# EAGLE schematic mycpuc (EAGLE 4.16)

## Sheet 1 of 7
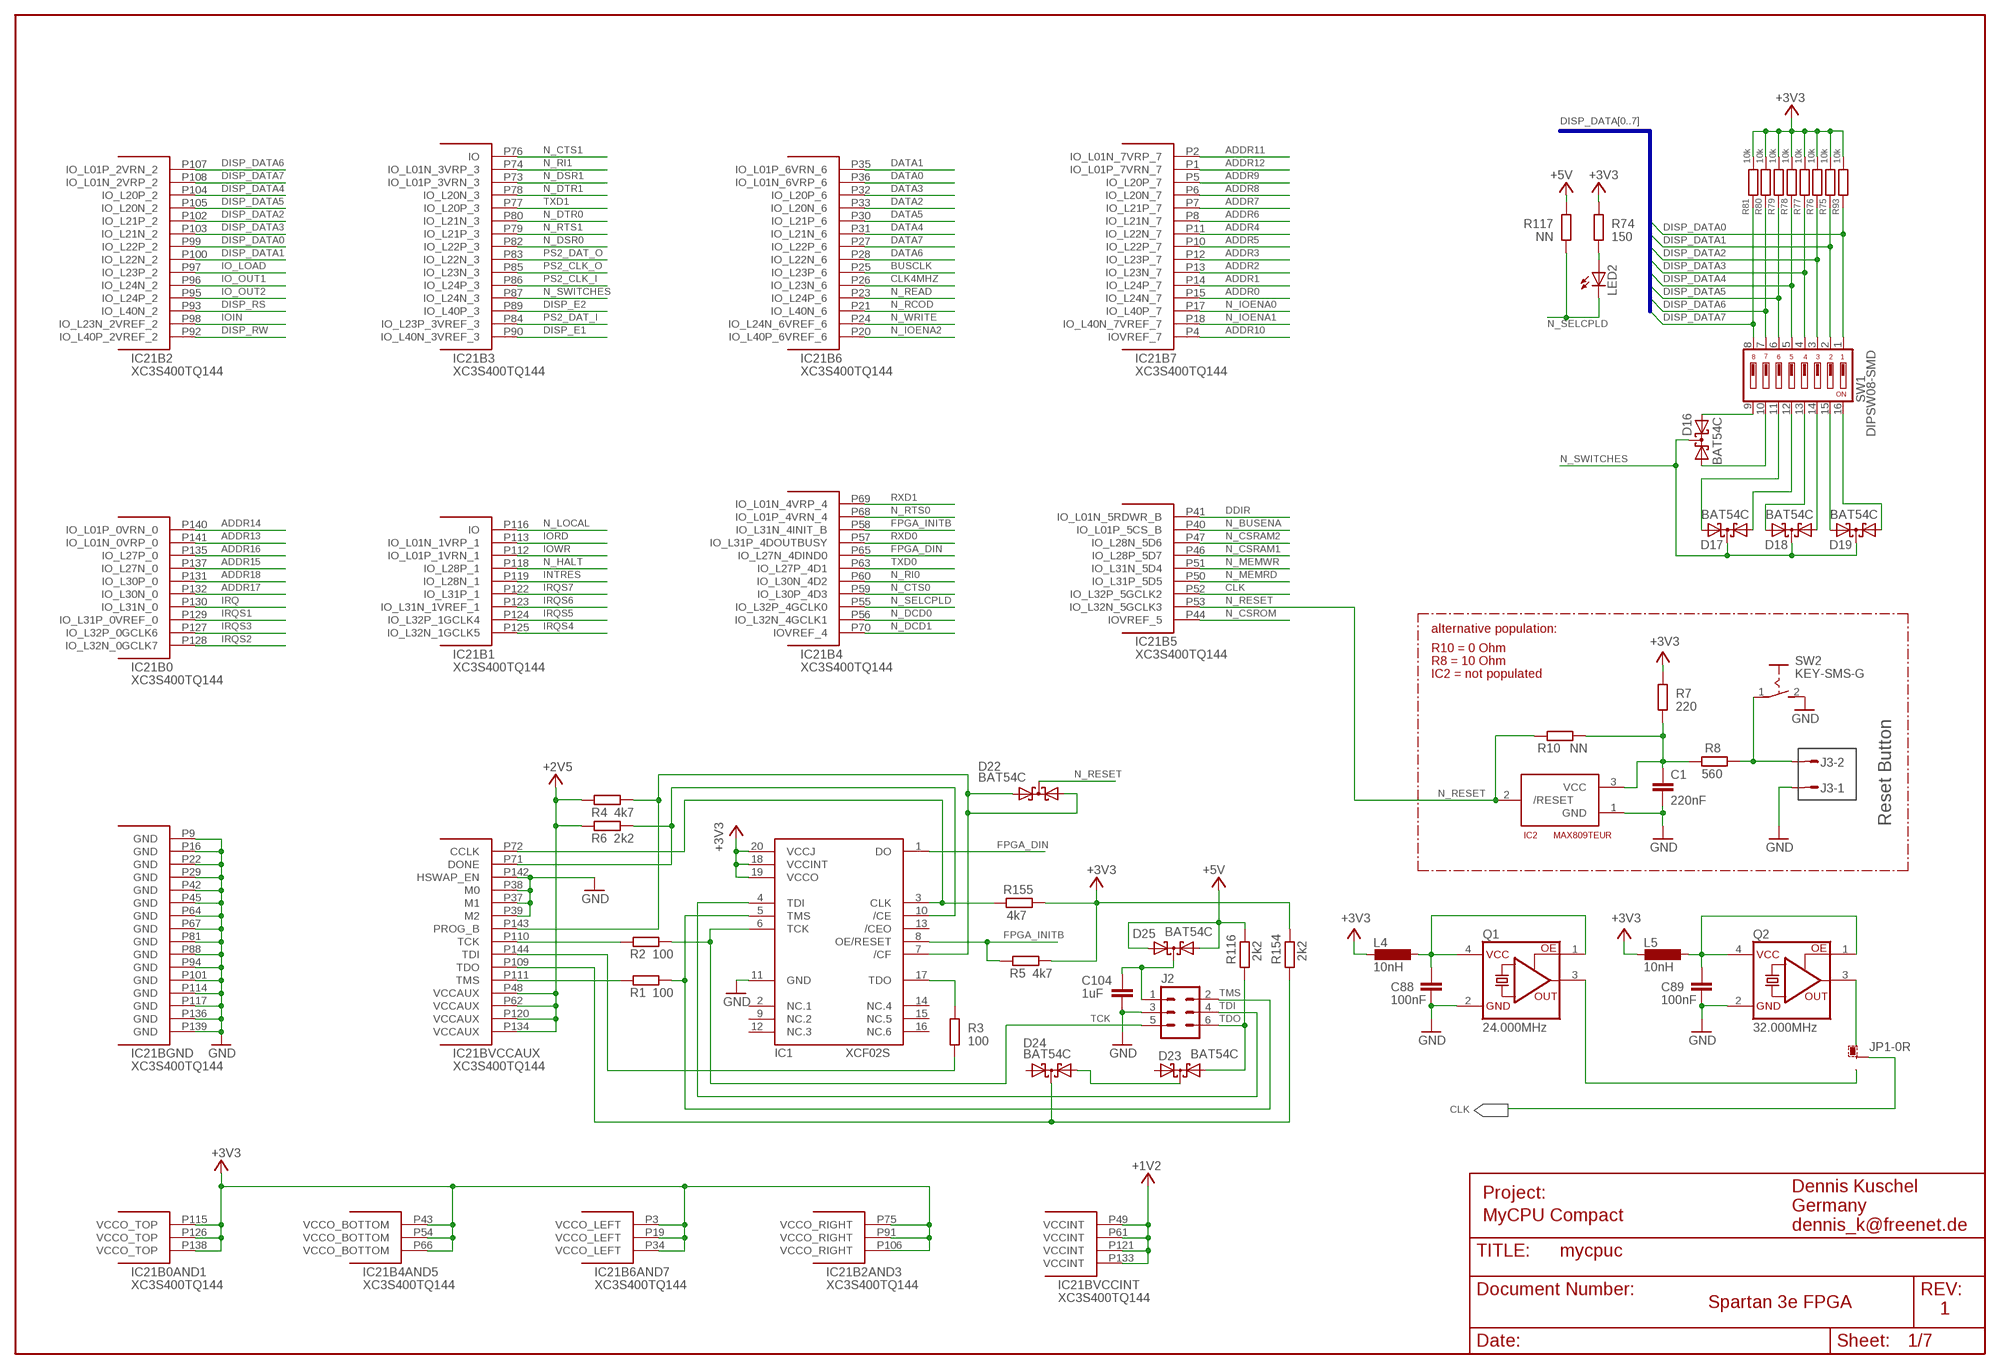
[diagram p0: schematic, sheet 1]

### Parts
C1  220nF  C-EUC0805  [C0805]
C88  100nF  C-EUC0805  [C0805]
C89  100nF  C-EUC0805  [C0805]
C104  1uF  C-EUC0805  [C0805]
D16  BAT54C  BAS40-05  [SOT23]
D17  BAT54C  BAS40-05  [SOT23]
D18  BAT54C  BAS40-05  [SOT23]
D19  BAT54C  BAS40-05  [SOT23]
D22  BAT54C  BAS40-05  [SOT23]
D23  BAT54C  BAS40-05  [SOT23]
D24  BAT54C  BAS40-05  [SOT23]
D25  BAT54C  BAS40-05  [SOT23]
IC1  XCF02S  [VO20]
IC2  MAX809TEUR  MAX809  [SOT23]
IC21  XC3S400TQ144  [TQ144]
J2  ML6  [ML6]
J3  S02P  [S02P]
JP1  0R-JUMPA  [A0R-JMP]
L4  10nH  L-0805  [0805]
L5  10nH  L-0805  [0805]
LED2  LEDCHIP-LED0805  [CHIP-LED0805]
Q1  24.000MHz  XO91  [XO91]
Q2  32.000MHz  XO91  [XO91]
R1  100  R-EU_M0805  [M0805]
R2  100  R-EU_M0805  [M0805]
R3  100  R-EU_M0805  [M0805]
R4  4k7  R-EU_M0805  [M0805]
R5  4k7  R-EU_M0805  [M0805]
R6  2k2  R-EU_M0805  [M0805]
R7  220  R-EU_M0805  [M0805]
R8  560  R-EU_M0805  [M0805]
R10  NN  R-EU_M0805  [M0805]
R74  150  R-EU_M0805  [M0805]
R75  10k  R-EU_M0805  [M0805]
R76  10k  R-EU_M0805  [M0805]
R77  10k  R-EU_M0805  [M0805]
R78  10k  R-EU_M0805  [M0805]
R79  10k  R-EU_M0805  [M0805]
R80  10k  R-EU_M0805  [M0805]
R81  10k  R-EU_M0805  [M0805]
R93  10k  R-EU_M0805  [M0805]
R116  2k2  R-EU_M0805  [M0805]
R117  NN  R-EU_M0805  [M0805]
R154  2k2  R-EU_M0805  [M0805]
R155  4k7  R-EU_M0805  [M0805]
SW1  DIPSW08-SMD  [DIPSW08]
SW2  KEY-SMS-G  [DIGIKEY-1]

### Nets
+1V2: IC21.P49(BVCCINT:VCCINT) IC21.P61(BVCCINT:VCCINT) IC21.P121(BVCCINT:VCCINT) IC21.P133(BVCCINT:VCCINT) ; also sheet 2
+2V5: IC21.P48(BVCCAUX:VCCAUX) IC21.P62(BVCCAUX:VCCAUX) IC21.P120(BVCCAUX:VCCAUX) IC21.P134(BVCCAUX:VCCAUX) R4.1 R6.1 ; also sheet 2
+3V3: IC1.18(VCCINT) IC1.19(VCCO) IC1.20(VCCJ) IC21.P3(B6AND7:VCCO_LEFT) IC21.P19(B6AND7:VCCO_LEFT) IC21.P34(B6AND7:VCCO_LEFT) IC21.P43(B4AND5:VCCO_BOTTOM) IC21.P54(B4AND5:VCCO_BOTTOM) IC21.P66(B4AND5:VCCO_BOTTOM) IC21.P75(B2AND3:VCCO_RIGHT) IC21.P91(B2AND3:VCCO_RIGHT) IC21.P106(B2AND3:VCCO_RIGHT) IC21.P115(B0AND1:VCCO_TOP) IC21.P126(B0AND1:VCCO_TOP) IC21.P138(B0AND1:VCCO_TOP) L4.2 L5.2 R5.2 R7.2 R74.2 R75.2 R76.2 R77.2 R78.2 R79.2 R80.2 R81.2 R93.2 R154.2 R155.2 ; also sheet 2,3,4,5
+5V: D25.1(A1) D25.2(A2) R116.2 R117.2 ; also sheet 2,3,5,6,7
ADDR0: IC21.P15(B7:IO_L24N_7) ; also sheet 3,4
ADDR1: IC21.P14(B7:IO_L24P_7) ; also sheet 3,4
ADDR2: IC21.P13(B7:IO_L23N_7) ; also sheet 3,4
ADDR3: IC21.P12(B7:IO_L23P_7) ; also sheet 3,4
ADDR4: IC21.P11(B7:IO_L22N_7) ; also sheet 3,4
ADDR5: IC21.P10(B7:IO_L22P_7) ; also sheet 3,4
ADDR6: IC21.P8(B7:IO_L21N_7) ; also sheet 3,4
ADDR7: IC21.P7(B7:IO_L21P_7) ; also sheet 3,4
ADDR8: IC21.P6(B7:IO_L20N_7) ; also sheet 3,4
ADDR9: IC21.P5(B7:IO_L20P_7) ; also sheet 3,4
ADDR10: IC21.P4(B7:IOVREF_7) ; also sheet 3,4
ADDR11: IC21.P2(B7:IO_L01N_7VRP_7) ; also sheet 3,4
ADDR12: IC21.P1(B7:IO_L01P_7VRN_7) ; also sheet 3,4
ADDR13: IC21.P141(B0:IO_L01N_0VRP_0) ; also sheet 3,4
ADDR14: IC21.P140(B0:IO_L01P_0VRN_0) ; also sheet 3,4
ADDR15: IC21.P137(B0:IO_L27N_0) ; also sheet 3,4
ADDR16: IC21.P135(B0:IO_L27P_0) ; also sheet 4
ADDR17: IC21.P132(B0:IO_L30N_0) ; also sheet 4
ADDR18: IC21.P131(B0:IO_L30P_0) ; also sheet 4
BUSCLK: IC21.P25(B6:IO_L23P_6) ; also sheet 3
CLK: IC21.P52(B5:IO_L32P_5GCLK2) JP1.2
CLK4MHZ: IC21.P26(B6:IO_L23N_6) ; also sheet 3,5
DATA0: IC21.P36(B6:IO_L01N_6VRP_6) ; also sheet 3,4
DATA1: IC21.P35(B6:IO_L01P_6VRN_6) ; also sheet 3,4
DATA2: IC21.P33(B6:IO_L20N_6) ; also sheet 3,4
DATA3: IC21.P32(B6:IO_L20P_6) ; also sheet 3,4
DATA4: IC21.P31(B6:IO_L21N_6) ; also sheet 3,4
DATA5: IC21.P30(B6:IO_L21P_6) ; also sheet 3,4
DATA6: IC21.P28(B6:IO_L22N_6) ; also sheet 3,4
DATA7: IC21.P27(B6:IO_L22P_6) ; also sheet 3,4
DDIR: IC21.P41(B5:IO_L01N_5RDWR_B) ; also sheet 3
DISP_DATA0: IC21.P99(B2:IO_L22P_2) R93.1 SW1.1 ; also sheet 5
DISP_DATA1: IC21.P100(B2:IO_L22N_2) R75.1 SW1.2 ; also sheet 5
DISP_DATA2: IC21.P102(B2:IO_L21P_2) R76.1 SW1.3 ; also sheet 5
DISP_DATA3: IC21.P103(B2:IO_L21N_2) R77.1 SW1.4 ; also sheet 5
DISP_DATA4: IC21.P104(B2:IO_L20P_2) R78.1 SW1.5 ; also sheet 5
DISP_DATA5: IC21.P105(B2:IO_L20N_2) R79.1 SW1.6 ; also sheet 5
DISP_DATA6: IC21.P107(B2:IO_L01P_2VRN_2) R80.1 SW1.7 ; also sheet 5
DISP_DATA7: IC21.P108(B2:IO_L01N_2VRP_2) R81.1 SW1.8 ; also sheet 5
DISP_E1: IC21.P90(B3:IO_L40N_3VREF_3) ; also sheet 5
DISP_E2: IC21.P89(B3:IO_L40P_3) ; also sheet 5
DISP_RS: IC21.P93(B2:IO_L40N_2) ; also sheet 5
DISP_RW: IC21.P92(B2:IO_L40P_2VREF_2) ; also sheet 5
FPGA_DIN: IC1.1(DO) IC21.P65(B4:IO_L27N_4DIND0)
FPGA_INITB: IC1.8(OE/RESET) IC21.P58(B4:IO_L31N_4INIT_B) R5.1 ; also sheet 7
GND: C1.2 C88.2 C89.2 C104.2 IC1.11(GND) IC2.1(GND) IC21.P9(BGND:GND) IC21.P16(BGND:GND) IC21.P22(BGND:GND) IC21.P29(BGND:GND) IC21.P37(BVCCAUX:M1) IC21.P38(BVCCAUX:M0) IC21.P39(BVCCAUX:M2) IC21.P42(BGND:GND) IC21.P45(BGND:GND) IC21.P64(BGND:GND) IC21.P67(BGND:GND) IC21.P81(BGND:GND) IC21.P88(BGND:GND) IC21.P94(BGND:GND) IC21.P101(BGND:GND) IC21.P114(BGND:GND) IC21.P117(BGND:GND) IC21.P136(BGND:GND) IC21.P139(BGND:GND) IC21.P142(BVCCAUX:HSWAP_EN) J2.3 J3.1 Q1.2(GND) Q2.2(GND) SW2.2 ; also sheet 2,3,4,5,6,7
INTRES: IC21.P119(B1:IO_L28N_1) ; also sheet 3
IO_LOAD: IC21.P97(B2:IO_L23P_2) ; also sheet 5
IO_OUT1: IC21.P96(B2:IO_L24N_2) ; also sheet 5
IO_OUT2: IC21.P95(B2:IO_L24P_2) ; also sheet 5
IOIN: IC21.P98(B2:IO_L23N_2VREF_2) ; also sheet 3,6
IORD: IC21.P113(B1:IO_L01N_1VRP_1) ; also sheet 3
IOWR: IC21.P112(B1:IO_L01P_1VRN_1) ; also sheet 3
IRQ: IC21.P130(B0:IO_L31N_0) ; also sheet 3
IRQS1: IC21.P129(B0:IO_L31P_0VREF_0) ; also sheet 3
IRQS2: IC21.P128(B0:IO_L32N_0GCLK7) ; also sheet 3
IRQS3: IC21.P127(B0:IO_L32P_0GCLK6) ; also sheet 3
IRQS4: IC21.P125(B1:IO_L32N_1GCLK5) ; also sheet 3
IRQS5: IC21.P124(B1:IO_L32P_1GCLK4) ; also sheet 3
IRQS6: IC21.P123(B1:IO_L31N_1VREF_1) ; also sheet 3
IRQS7: IC21.P122(B1:IO_L31P_1) ; also sheet 3
N$1: J3.2 R8.2 SW2.1
N$2: IC1.3(CLK) IC21.P72(BVCCAUX:CCLK) R155.1
N$3: IC1.10(/CE) IC21.P71(BVCCAUX:DONE) R6.2
N$4: IC21.P111(BVCCAUX:TMS) R1.1
N$5: IC21.P110(BVCCAUX:TCK) R2.1
N$6: C1.1 IC2.3(VCC) R7.1 R8.1 R10.2
N$8: IC1.17(TDO) R3.2
N$9: IC21.P144(BVCCAUX:TDI) R3.1
N$10: D22.1(A1) D22.2(A2) IC1.7(/CF) IC21.P143(BVCCAUX:PROG_B) R4.2
N$19: C104.1 D25.3(C) J2.1
N$52: LED2.A R74.1
N$53: D16.2(A2) SW1.9
N$54: D16.1(A1) SW1.10
N$55: D17.2(A2) SW1.11
N$56: D17.1(A1) SW1.12
N$57: D18.2(A2) SW1.13
N$58: D18.1(A1) SW1.14
N$59: D19.2(A2) SW1.15
N$60: D19.1(A1) SW1.16
N$65: JP1.1 Q2.3(FO)
N$66: JP1.3 Q1.3(FO)
N$103: D23.3(C) D24.1(A1)
N_BUSENA: IC21.P40(B5:IO_L01P_5CS_B) ; also sheet 3
N_CSRAM1: IC21.P46(B5:IO_L28P_5D7) ; also sheet 4
N_CSRAM2: IC21.P47(B5:IO_L28N_5D6) ; also sheet 4
N_CSROM: IC21.P44(B5:IOVREF_5) ; also sheet 4
N_CTS0: IC21.P59(B4:IO_L30P_4D3) ; also sheet 5
N_CTS1: IC21.P76(B3:IO) ; also sheet 5
N_DCD0: IC21.P56(B4:IO_L32N_4GCLK1) ; also sheet 5
N_DCD1: IC21.P70(B4:IOVREF_4) ; also sheet 5
N_DSR0: IC21.P82(B3:IO_L22P_3) ; also sheet 5
N_DSR1: IC21.P73(B3:IO_L01P_3VRN_3) ; also sheet 5
N_DTR0: IC21.P80(B3:IO_L21N_3) ; also sheet 5
N_DTR1: IC21.P78(B3:IO_L20N_3) ; also sheet 5
N_HALT: IC21.P118(B1:IO_L28P_1) ; also sheet 3
N_IOENA0: IC21.P17(B7:IO_L40P_7) ; also sheet 3
N_IOENA1: IC21.P18(B7:IO_L40N_7VREF_7) ; also sheet 3
N_IOENA2: IC21.P20(B6:IO_L40P_6VREF_6) ; also sheet 3
N_LOCAL: IC21.P116(B1:IO) ; also sheet 3
N_MEMRD: IC21.P50(B5:IO_L31P_5D5) ; also sheet 4
N_MEMWR: IC21.P51(B5:IO_L31N_5D4) ; also sheet 4
N_RCOD: IC21.P21(B6:IO_L40N_6) ; also sheet 3
N_READ: IC21.P23(B6:IO_L24P_6) ; also sheet 3
N_RESET: D22.3(C) IC2.2(/RESET) IC21.P53(B5:IO_L32N_5GCLK3) R10.1 ; also sheet 4
N_RI0: IC21.P60(B4:IO_L30N_4D2) ; also sheet 5
N_RI1: IC21.P74(B3:IO_L01N_3VRP_3) ; also sheet 5
N_RTS0: IC21.P68(B4:IO_L01P_4VRN_4) ; also sheet 5
N_RTS1: IC21.P79(B3:IO_L21P_3) ; also sheet 5
N_SELCPLD: IC21.P55(B4:IO_L32P_4GCLK0) LED2.C R117.1 ; also sheet 7
N_SWITCHES: D16.3(C) D17.3(C) D18.3(C) D19.3(C) IC21.P87(B3:IO_L24N_3)
N_WRITE: IC21.P24(B6:IO_L24N_6VREF_6) ; also sheet 3
PS2_CLK_I: IC21.P86(B3:IO_L24P_3) ; also sheet 5
PS2_CLK_O: IC21.P85(B3:IO_L23N_3) ; also sheet 5
PS2_DAT_I: IC21.P84(B3:IO_L23P_3VREF_3) ; also sheet 5
PS2_DAT_O: IC21.P83(B3:IO_L22N_3) ; also sheet 5
Q1_3V3: C88.1 L4.1 Q1.1(OE) Q1.4(VCC)
Q2_3V3: C89.1 L5.1 Q2.1(OE) Q2.4(VCC)
RXD0: IC21.P57(B4:IO_L31P_4DOUTBUSY) ; also sheet 5
RXD1: IC21.P69(B4:IO_L01N_4VRP_4) ; also sheet 5
TCK: IC1.6(TCK) J2.5 R2.2
TDI: IC1.4(TDI) J2.4
TDO: D24.3(C) IC21.P109(BVCCAUX:TDO) R154.1
TDO_JTAG: D23.1(A1) J2.6 R116.1
TMS: IC1.5(TMS) J2.2 R1.2
TXD0: IC21.P63(B4:IO_L27P_4D1) ; also sheet 5
TXD1: IC21.P77(B3:IO_L20P_3) ; also sheet 5
Unconnected: D23.2(A2) D24.2(A2) IC1.2(NC.1) IC1.9(NC.2) IC1.12(NC.3) IC1.13(/CEO) IC1.14(NC.4) IC1.15(NC.5) IC1.16(NC.6)

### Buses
DISP_DATA[0..7]

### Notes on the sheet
- alternative population:
- R10 = 0 Ohm
- R8 = 10 Ohm
- IC2 = not populated
- Reset Button
- Dennis Kuschel
- Project:
- Germany
- MyCPU Compact
- dennis_k@freenet.de
- Spartan 3e FPGA
- 1

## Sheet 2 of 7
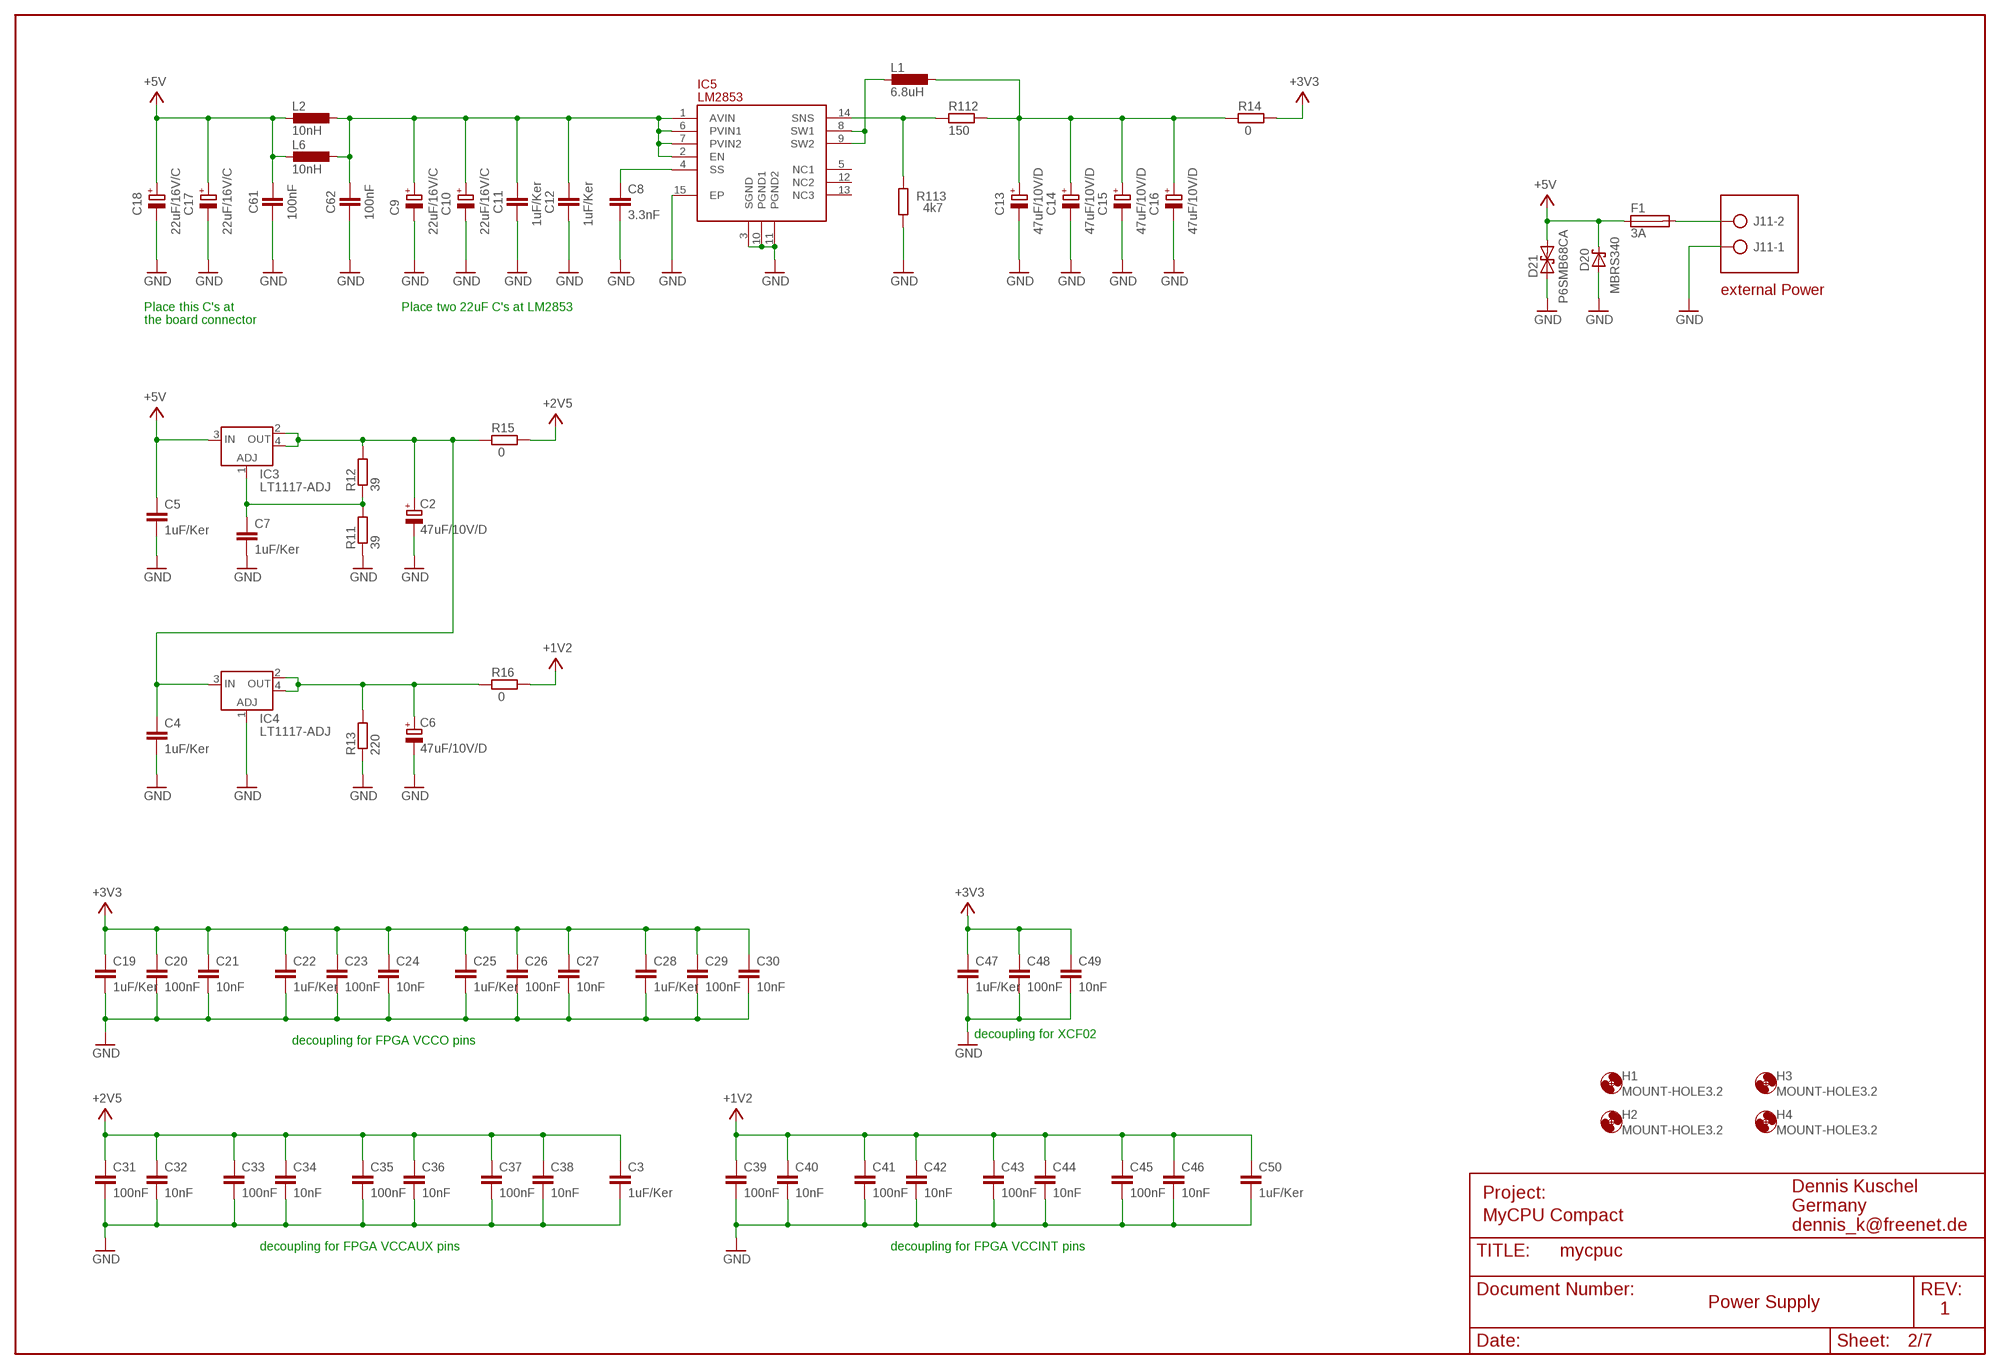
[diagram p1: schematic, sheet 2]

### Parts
C2  47uF/10V/D  CPOL-EUD/7343-31R  [D/7343-31R]
C3  1uF/Ker  C-EUC0805  [C0805]
C4  1uF/Ker  C-EUC0805  [C0805]
C5  1uF/Ker  C-EUC0805  [C0805]
C6  47uF/10V/D  CPOL-EUD/7343-31R  [D/7343-31R]
C7  1uF/Ker  C-EUC0805  [C0805]
C8  3.3nF  C-EUC0805  [C0805]
C9  22uF/16V/C  CPOL-EUC/6032-28R  [C/6032-28R]
C10  22uF/16V/C  CPOL-EUC/6032-28R  [C/6032-28R]
C11  1uF/Ker  C-EUC0805  [C0805]
C12  1uF/Ker  C-EUC0805  [C0805]
C13  47uF/10V/D  CPOL-EUD/7343-31R  [D/7343-31R]
C14  47uF/10V/D  CPOL-EUD/7343-31R  [D/7343-31R]
C15  47uF/10V/D  CPOL-EUD/7343-31R  [D/7343-31R]
C16  47uF/10V/D  CPOL-EUD/7343-31R  [D/7343-31R]
C17  22uF/16V/C  CPOL-EUC/6032-28R  [C/6032-28R]
C18  22uF/16V/C  CPOL-EUC/6032-28R  [C/6032-28R]
C19  1uF/Ker  C-EUC0805  [C0805]
C20  100nF  C-EUC0805  [C0805]
C21  10nF  C-EUC0805  [C0805]
C22  1uF/Ker  C-EUC0805  [C0805]
C23  100nF  C-EUC0805  [C0805]
C24  10nF  C-EUC0805  [C0805]
C25  1uF/Ker  C-EUC0805  [C0805]
C26  100nF  C-EUC0805  [C0805]
C27  10nF  C-EUC0805  [C0805]
C28  1uF/Ker  C-EUC0805  [C0805]
C29  100nF  C-EUC0805  [C0805]
C30  10nF  C-EUC0805  [C0805]
C31  100nF  C-EUC0805  [C0805]
C32  10nF  C-EUC0805  [C0805]
C33  100nF  C-EUC0805  [C0805]
C34  10nF  C-EUC0805  [C0805]
C35  100nF  C-EUC0805  [C0805]
C36  10nF  C-EUC0805  [C0805]
C37  100nF  C-EUC0805  [C0805]
C38  10nF  C-EUC0805  [C0805]
C39  100nF  C-EUC0805  [C0805]
C40  10nF  C-EUC0805  [C0805]
C41  100nF  C-EUC0805  [C0805]
C42  10nF  C-EUC0805  [C0805]
C43  100nF  C-EUC0805  [C0805]
C44  10nF  C-EUC0805  [C0805]
C45  100nF  C-EUC0805  [C0805]
C46  10nF  C-EUC0805  [C0805]
C47  1uF/Ker  C-EUC0805  [C0805]
C48  100nF  C-EUC0805  [C0805]
C49  10nF  C-EUC0805  [C0805]
C50  1uF/Ker  C-EUC0805  [C0805]
C61  100nF  C-EUC0805  [C0805]
C62  100nF  C-EUC0805  [C0805]
D20  MBRS340  [DO214AB]
D21  P6SMB68CA  [DO214AA]
F1  3A  FUSE-HASF  [HASF]
H1  MOUNT-HOLE3.2  [3,2]
H2  MOUNT-HOLE3.2  [3,2]
H3  MOUNT-HOLE3.2  [3,2]
H4  MOUNT-HOLE3.2  [3,2]
IC3  LT1117-ADJ  [SOT223]
IC4  LT1117-ADJ  [SOT223]
IC5  LM2853  [ETSSOP14]
J11  AK500/2  [AK500/2]
L1  6.8uH  DO3316P  [DO3316P]
L2  10nH  L-0805  [0805]
L6  10nH  L-0805  [0805]
R11  39  R-EU_R0805  [R0805]
R12  39  R-EU_R0805  [R0805]
R13  220  R-EU_R0805  [R0805]
R14  0  R-EU_R0805  [R0805]
R15  0  R-EU_R0805  [R0805]
R16  0  R-EU_R0805  [R0805]
R112  150  R-EU_R0805  [R0805]
R113  4k7  R-EU_R0805  [R0805]

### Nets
3V3OUT: C13.+ C14.+ C15.+ C16.+ L1.2 R14.1 R112.2
5V_SREG: C9.+ C10.+ C11.1 C12.1 C62.1 IC5.1(AVIN) IC5.2(EN) IC5.6(PVIN1) IC5.7(PVIN2) L2.1 L6.1
+1V2: C39.1 C40.1 C41.1 C42.1 C43.1 C44.1 C45.1 C46.1 C50.1 R16.2 ; also sheet 1
+2V5: C3.1 C31.1 C32.1 C33.1 C34.1 C35.1 C36.1 C37.1 C38.1 R15.2 ; also sheet 1
+3V3: C19.1 C20.1 C21.1 C22.1 C23.1 C24.1 C25.1 C26.1 C27.1 C28.1 C29.1 C30.1 C47.1 C48.1 C49.1 R14.2 ; also sheet 1,3,4,5
+5V: C5.1 C17.+ C18.+ C61.1 D20.K(C) D21.K(C) F1.1 IC3.3(IN) L2.2 L6.2 ; also sheet 1,3,5,6,7
GND: C2.- C3.2 C4.2 C5.2 C6.- C7.2 C8.2 C9.- C10.- C11.2 C12.2 C13.- C14.- C15.- C16.- C17.- C18.- C19.2 C20.2 C21.2 C22.2 C23.2 C24.2 C25.2 C26.2 C27.2 C28.2 C29.2 C30.2 C31.2 C32.2 C33.2 C34.2 C35.2 C36.2 C37.2 C38.2 C39.2 C40.2 C41.2 C42.2 C43.2 C44.2 C45.2 C46.2 C47.2 C48.2 C49.2 C50.2 C61.2 C62.2 D20.A D21.A IC4.1(ADJ) IC5.3(SGND) IC5.10(PGND1) IC5.11(PGND2) IC5.15(EP) J11.1 R11.1 R13.1 R113.1 ; also sheet 1,3,4,5,6,7
N$7: C7.1 IC3.1(ADJ) R11.2 R12.1
N$11: IC5.8(SW1) IC5.9(SW2) L1.1
N$13: C8.1 IC5.4(SS)
N$15: C6.+ IC4.2(OUT) IC4.4(OUT1) R13.2 R16.1
N$63: C2.+ C4.1 IC3.2(OUT) IC3.4(OUT1) IC4.3(IN) R12.2 R15.1
N$69: IC5.14(SNS) R112.1 R113.2
N$90: F1.2 J11.2
Unconnected: IC5.5(NC1) IC5.12(NC2) IC5.13(NC3)

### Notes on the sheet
- external Power
- Place this C's at | Place two 22uF C's at LM2853
- the board connector
- decoupling for XCF02
- decoupling for FPGA VCCO pins
- Dennis Kuschel
- Project:
- Germany
- MyCPU Compact
- dennis_k@freenet.de
- decoupling for FPGA VCCAUX pins | decoupling for FPGA VCCINT pins
- Power Supply
- 1

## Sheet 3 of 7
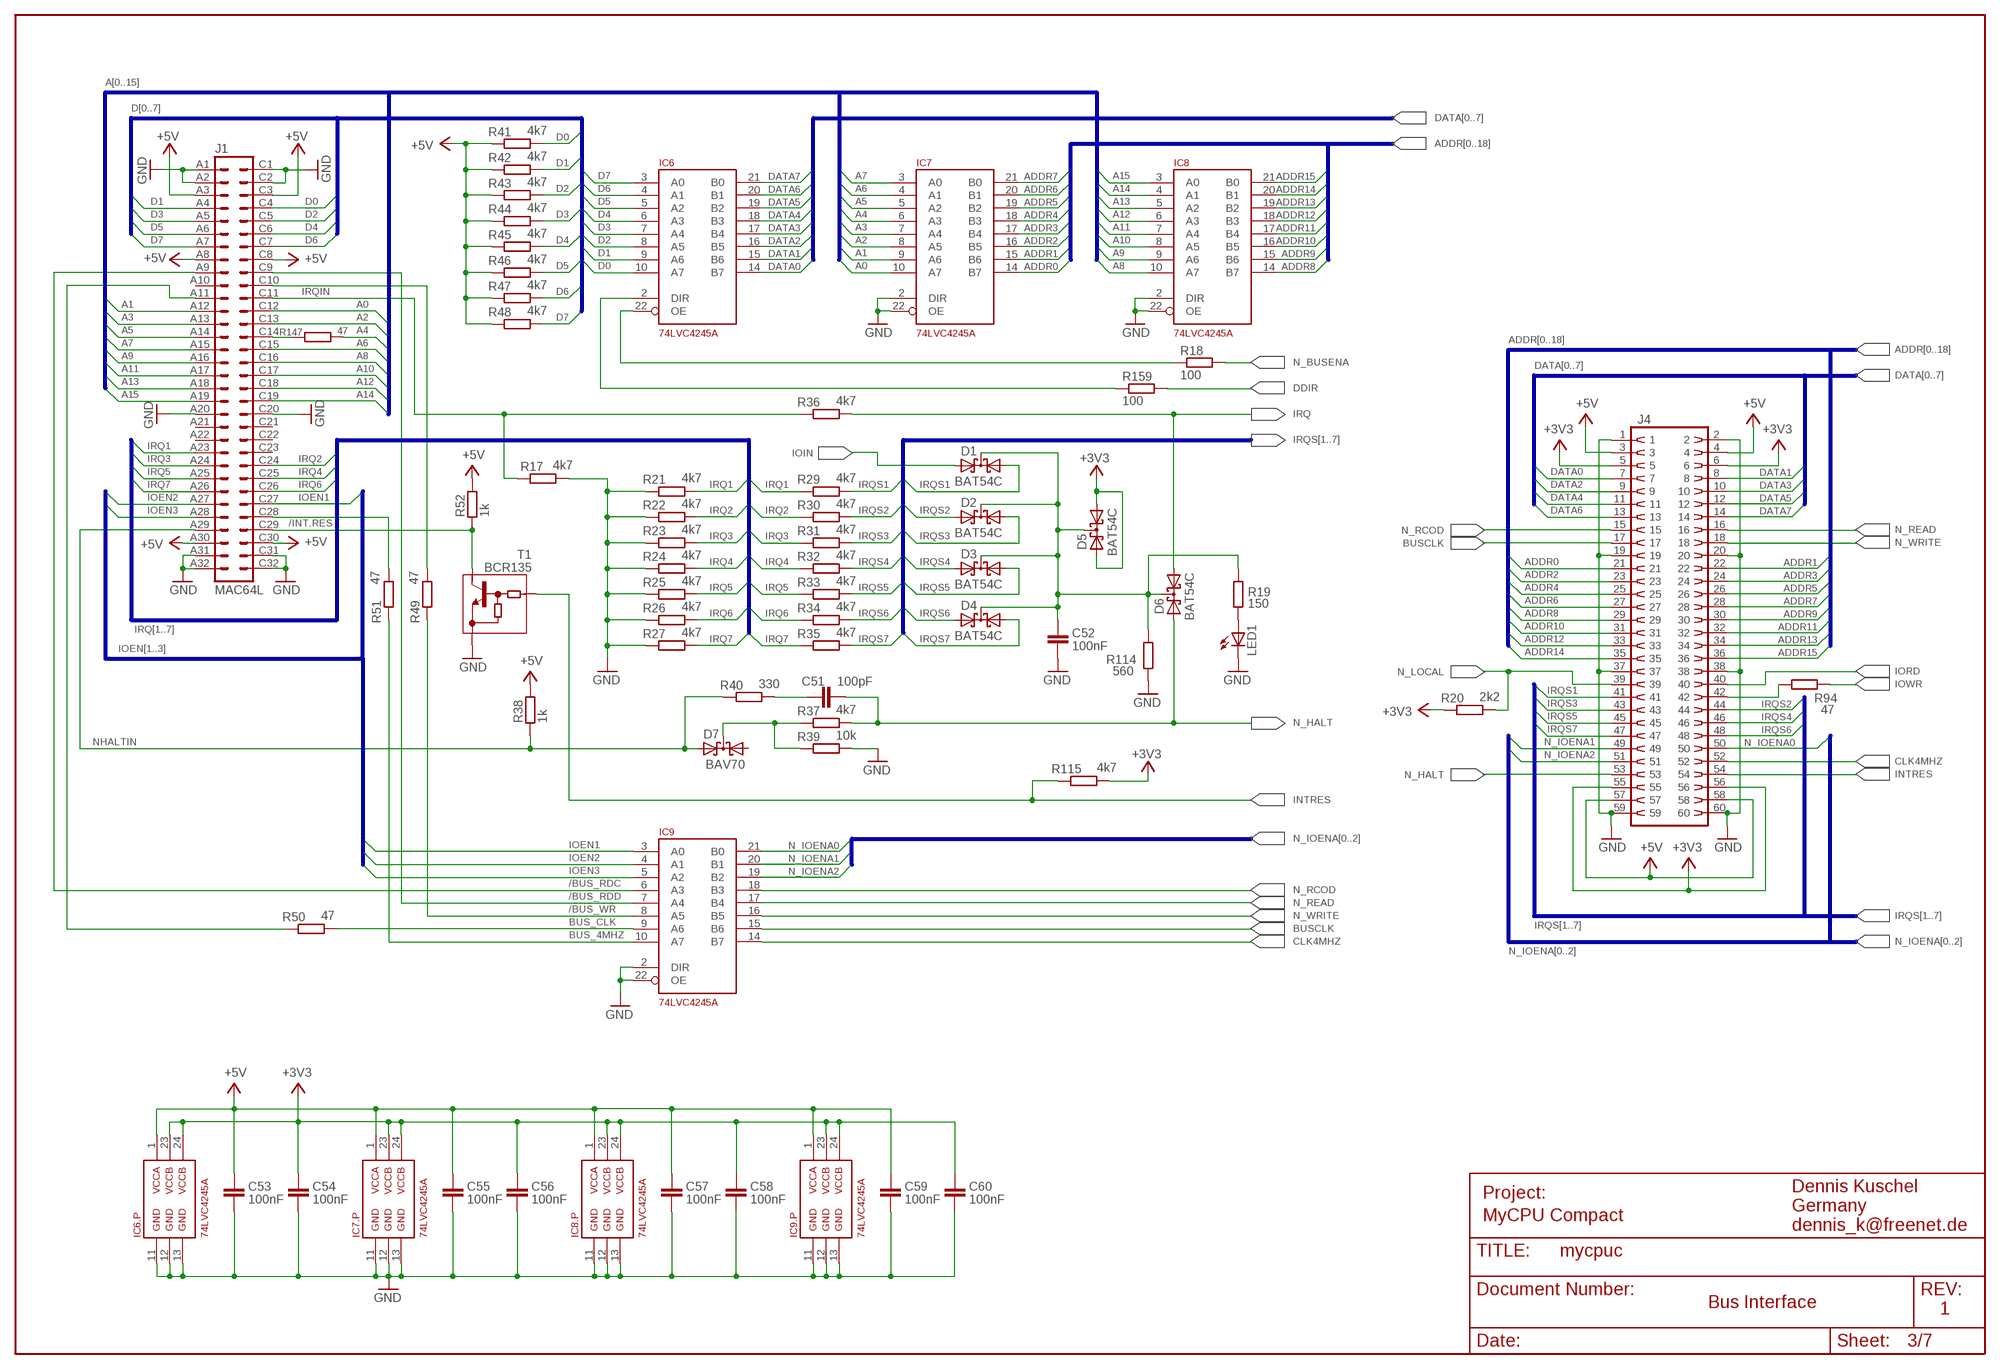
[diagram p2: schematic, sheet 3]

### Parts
C51  100pF  C-EUC0805  [C0805]
C52  100nF  C-EUC0805  [C0805]
C53  100nF  C-EUC0805  [C0805]
C54  100nF  C-EUC0805  [C0805]
C55  100nF  C-EUC0805  [C0805]
C56  100nF  C-EUC0805  [C0805]
C57  100nF  C-EUC0805  [C0805]
C58  100nF  C-EUC0805  [C0805]
C59  100nF  C-EUC0805  [C0805]
C60  100nF  C-EUC0805  [C0805]
D1  BAT54C  BAS40-05  [SOT23]
D2  BAT54C  BAS40-05  [SOT23]
D3  BAT54C  BAS40-05  [SOT23]
D4  BAT54C  BAS40-05  [SOT23]
D5  BAT54C  BAS40-05  [SOT23]
D6  BAT54C  BAS40-05  [SOT23]
D7  BAV70  BAS40-05  [SOT23]
IC6  74LVC4245A  [TSSOP24]
IC7  74LVC4245A  [TSSOP24]
IC8  74LVC4245A  [TSSOP24]
IC9  74LVC4245A  [TSSOP24]
J1  MAC64L  [MAC64L]
J4  BU60  [DIL2X30]
LED1  LEDCHIP-LED0805  [CHIP-LED0805]
R17  4k7  R-EU_R0805  [R0805]
R18  100  R-EU_R0805  [R0805]
R19  150  R-EU_R0805  [R0805]
R20  2k2  R-EU_R0805  [R0805]
R21  4k7  R-EU_R0805  [R0805]
R22  4k7  R-EU_R0805  [R0805]
R23  4k7  R-EU_R0805  [R0805]
R24  4k7  R-EU_R0805  [R0805]
R25  4k7  R-EU_R0805  [R0805]
R26  4k7  R-EU_R0805  [R0805]
R27  4k7  R-EU_R0805  [R0805]
R29  4k7  R-EU_R0805  [R0805]
R30  4k7  R-EU_R0805  [R0805]
R31  4k7  R-EU_R0805  [R0805]
R32  4k7  R-EU_R0805  [R0805]
R33  4k7  R-EU_R0805  [R0805]
R34  4k7  R-EU_R0805  [R0805]
R35  4k7  R-EU_R0805  [R0805]
R36  4k7  R-EU_R0805  [R0805]
R37  4k7  R-EU_R0805  [R0805]
R38  1k  R-EU_R0805  [R0805]
R39  10k  R-EU_R0805  [R0805]
R40  330  R-EU_R0805  [R0805]
R41  4k7  R-EU_R0805  [R0805]
R42  4k7  R-EU_R0805  [R0805]
R43  4k7  R-EU_R0805  [R0805]
R44  4k7  R-EU_R0805  [R0805]
R45  4k7  R-EU_R0805  [R0805]
R46  4k7  R-EU_R0805  [R0805]
R47  4k7  R-EU_R0805  [R0805]
R48  4k7  R-EU_R0805  [R0805]
R49  47  R-EU_R0805  [R0805]
R50  47  R-EU_R0805  [R0805]
R51  47  R-EU_R0805  [R0805]
R52  1k  R-EU_R0805  [R0805]
R94  47  R-EU_R0805  [R0805]
R114  560  R-EU_R0805  [R0805]
R115  4k7  R-EU_R0805  [R0805]
R147  47  R-EU_R0805  [R0805]
R159  100  R-EU_R0805  [R0805]
T1  BCR135  [SOT23]

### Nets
2V9: C52.1 D1.3(C) D2.3(C) D3.3(C) D4.3(C) D5.3(C) D6.3(C) R19.1 R114.1
4.000MHZ: J1.C28 R51.2
+3V3: C54.1 C56.1 C58.1 C60.1 D5.1(A1) D5.2(A2) IC6.23(VCCB.1) IC6.24(VCCB.2) IC7.23(VCCB.1) IC7.24(VCCB.2) IC8.23(VCCB.1) IC8.24(VCCB.2) IC9.23(VCCB.1) IC9.24(VCCB.2) J4.5 J4.6 J4.55 J4.56 R20.1 R115.2 ; also sheet 1,2,4,5
+5V: C53.1 C55.1 C57.1 C59.1 IC6.1(VCCA) IC7.1(VCCA) IC8.1(VCCA) IC9.1(VCCA) J1.A3 J1.A8 J1.A30 J1.C3 J1.C8 J1.C30 J4.3 J4.4 J4.57 J4.58 R38.2 R41.1 R42.1 R43.1 R44.1 R45.1 R46.1 R47.1 R48.1 R52.2 ; also sheet 1,2,5,6,7
/B_WR: J1.C10 R49.2
/BUS_RDC: IC9.6(A3) J1.A9
/BUS_RDD: IC9.7(A4) J1.C9 ; also sheet 7
/BUS_WR: IC9.8(A5) R49.1 ; also sheet 7
/INT.RES: J1.C29 R52.1 T1.3(C) ; also sheet 7
A0: IC7.10(A7) J1.C12 ; also sheet 7
A1: IC7.9(A6) J1.A12 ; also sheet 7
A2: IC7.8(A5) J1.C13 ; also sheet 7
A3: IC7.7(A4) J1.A13 ; also sheet 7
A4: IC7.6(A3) R147.2 ; also sheet 7
A4B: J1.C14 R147.1
A5: IC7.5(A2) J1.A14 ; also sheet 7
A6: IC7.4(A1) J1.C15
A7: IC7.3(A0) J1.A15
A8: IC8.10(A7) J1.C16 ; also sheet 7
A9: IC8.9(A6) J1.A16 ; also sheet 7
A10: IC8.8(A5) J1.C17
A11: IC8.7(A4) J1.A17
A12: IC8.6(A3) J1.C18
A13: IC8.5(A2) J1.A18
A14: IC8.4(A1) J1.C19
A15: IC8.3(A0) J1.A19
ADDR0: IC7.14(B7) J4.21 ; also sheet 1,4
ADDR1: IC7.15(B6) J4.22 ; also sheet 1,4
ADDR2: IC7.16(B5) J4.23 ; also sheet 1,4
ADDR3: IC7.17(B4) J4.24 ; also sheet 1,4
ADDR4: IC7.18(B3) J4.25 ; also sheet 1,4
ADDR5: IC7.19(B2) J4.26 ; also sheet 1,4
ADDR6: IC7.20(B1) J4.27 ; also sheet 1,4
ADDR7: IC7.21(B0) J4.28 ; also sheet 1,4
ADDR8: IC8.14(B7) J4.29 ; also sheet 1,4
ADDR9: IC8.15(B6) J4.30 ; also sheet 1,4
ADDR10: IC8.16(B5) J4.31 ; also sheet 1,4
ADDR11: IC8.17(B4) J4.32 ; also sheet 1,4
ADDR12: IC8.18(B3) J4.33 ; also sheet 1,4
ADDR13: IC8.19(B2) J4.34 ; also sheet 1,4
ADDR14: IC8.20(B1) J4.35 ; also sheet 1,4
ADDR15: IC8.21(B0) J4.36 ; also sheet 1,4
BUS_4MHZ: IC9.10(A7) R51.1
BUS_CLK: IC9.9(A6) R50.2
BUSCKOUT: J1.A11 R50.1
BUSCLK: IC9.15(B6) J4.17 ; also sheet 1
CLK4MHZ: IC9.14(B7) J4.52 ; also sheet 1,5
D0: IC6.10(A7) J1.C4 R41.2 ; also sheet 7
D1: IC6.9(A6) J1.A4 R42.2 ; also sheet 7
D2: IC6.8(A5) J1.C5 R43.2 ; also sheet 7
D3: IC6.7(A4) J1.A5 R44.2 ; also sheet 7
D4: IC6.6(A3) J1.C6 R45.2 ; also sheet 7
D5: IC6.5(A2) J1.A6 R46.2 ; also sheet 7
D6: IC6.4(A1) J1.C7 R47.2 ; also sheet 7
D7: IC6.3(A0) J1.A7 R48.2 ; also sheet 7
DATA0: IC6.14(B7) J4.7 ; also sheet 1,4
DATA1: IC6.15(B6) J4.8 ; also sheet 1,4
DATA2: IC6.16(B5) J4.9 ; also sheet 1,4
DATA3: IC6.17(B4) J4.10 ; also sheet 1,4
DATA4: IC6.18(B3) J4.11 ; also sheet 1,4
DATA5: IC6.19(B2) J4.12 ; also sheet 1,4
DATA6: IC6.20(B1) J4.13 ; also sheet 1,4
DATA7: IC6.21(B0) J4.14 ; also sheet 1,4
DDIR: R159.2 ; also sheet 1
GND: C52.2 C53.2 C54.2 C55.2 C56.2 C57.2 C58.2 C59.2 C60.2 IC6.11(GND.1) IC6.12(GND.2) IC6.13(GND.3) IC7.2(DIR) IC7.11(GND.1) IC7.12(GND.2) IC7.13(GND.3) IC7.22(OE) IC8.2(DIR) IC8.11(GND.1) IC8.12(GND.2) IC8.13(GND.3) IC8.22(OE) IC9.2(DIR) IC9.11(GND.1) IC9.12(GND.2) IC9.13(GND.3) IC9.22(OE) J1.A1 J1.A2 J1.A20 J1.A31 J1.A32 J1.C1 J1.C2 J1.C20 J1.C31 J1.C32 J4.1 J4.2 J4.19 J4.20 J4.37 J4.38 J4.59 J4.60 LED1.C R17.2 R21.1 R22.1 R23.1 R24.1 R25.1 R26.1 R27.1 R39.2 R114.2 T1.2(E) ; also sheet 1,2,4,5,6,7
INTRES: J4.54 R115.1 T1.1(B) ; also sheet 1
IOEN1: IC9.3(A0) J1.C27
IOEN2: IC9.4(A1) J1.A27
IOEN3: IC9.5(A2) J1.A28
IOIN: D1.2(A2) ; also sheet 1,6
IORD: J4.40 ; also sheet 1
IOWR: R94.2 ; also sheet 1
IOWR_R: J4.42 R94.1
IRQ: D6.1(A1) R36.2 ; also sheet 1
IRQ1: J1.A23 R21.2 R29.1
IRQ2: J1.C24 R22.2 R30.1
IRQ3: J1.A24 R23.2 R31.1
IRQ4: J1.C25 R24.2 R32.1
IRQ5: J1.A25 R25.2 R33.1
IRQ6: J1.C26 R26.2 R34.1
IRQ7: J1.A26 R27.2 R35.1
IRQIN: J1.C11 R17.1 R36.1
IRQS1: D1.1(A1) J4.41 R29.2 ; also sheet 1
IRQS2: D2.2(A2) J4.44 R30.2 ; also sheet 1
IRQS3: D2.1(A1) J4.43 R31.2 ; also sheet 1
IRQS4: D3.2(A2) J4.46 R32.2 ; also sheet 1
IRQS5: D3.1(A1) J4.45 R33.2 ; also sheet 1
IRQS6: D4.2(A2) J4.48 R34.2 ; also sheet 1
IRQS7: D4.1(A1) J4.47 R35.2 ; also sheet 1
N$16: IC6.22(OE) R18.1
N$17: C51.1 R40.2
N$18: D7.3(C) R37.1 R39.1
N$35: IC6.2(DIR) R159.1
N$51: LED1.A R19.2
N_BUSENA: R18.2 ; also sheet 1
N_HALT: C51.2 D6.2(A2) J4.53 R37.2 ; also sheet 1
N_IOENA0: IC9.21(B0) J4.50 ; also sheet 1
N_IOENA1: IC9.20(B1) J4.49 ; also sheet 1
N_IOENA2: IC9.19(B2) J4.51 ; also sheet 1
N_LOCAL: J4.39 R20.2 ; also sheet 1
N_RCOD: IC9.18(B3) J4.15 ; also sheet 1
N_READ: IC9.17(B4) J4.16 ; also sheet 1
N_WRITE: IC9.16(B5) J4.18 ; also sheet 1
NHALTIN: D7.2(A2) J1.A29 R38.1 R40.1
Unconnected: D7.1(A1) J1.A10 J1.A21 J1.A22 J1.C21 J1.C22 J1.C23

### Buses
D[0..7]
A[0..15]
IRQ[1..7]
IOEN[1..3]
ADDR[0..18]
DATA[0..7]
IRQS[1..7]
N_IOENA[0..2]

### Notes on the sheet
- Dennis Kuschel
- Project:
- Germany
- MyCPU Compact
- dennis_k@freenet.de
- Bus Interface
- 1

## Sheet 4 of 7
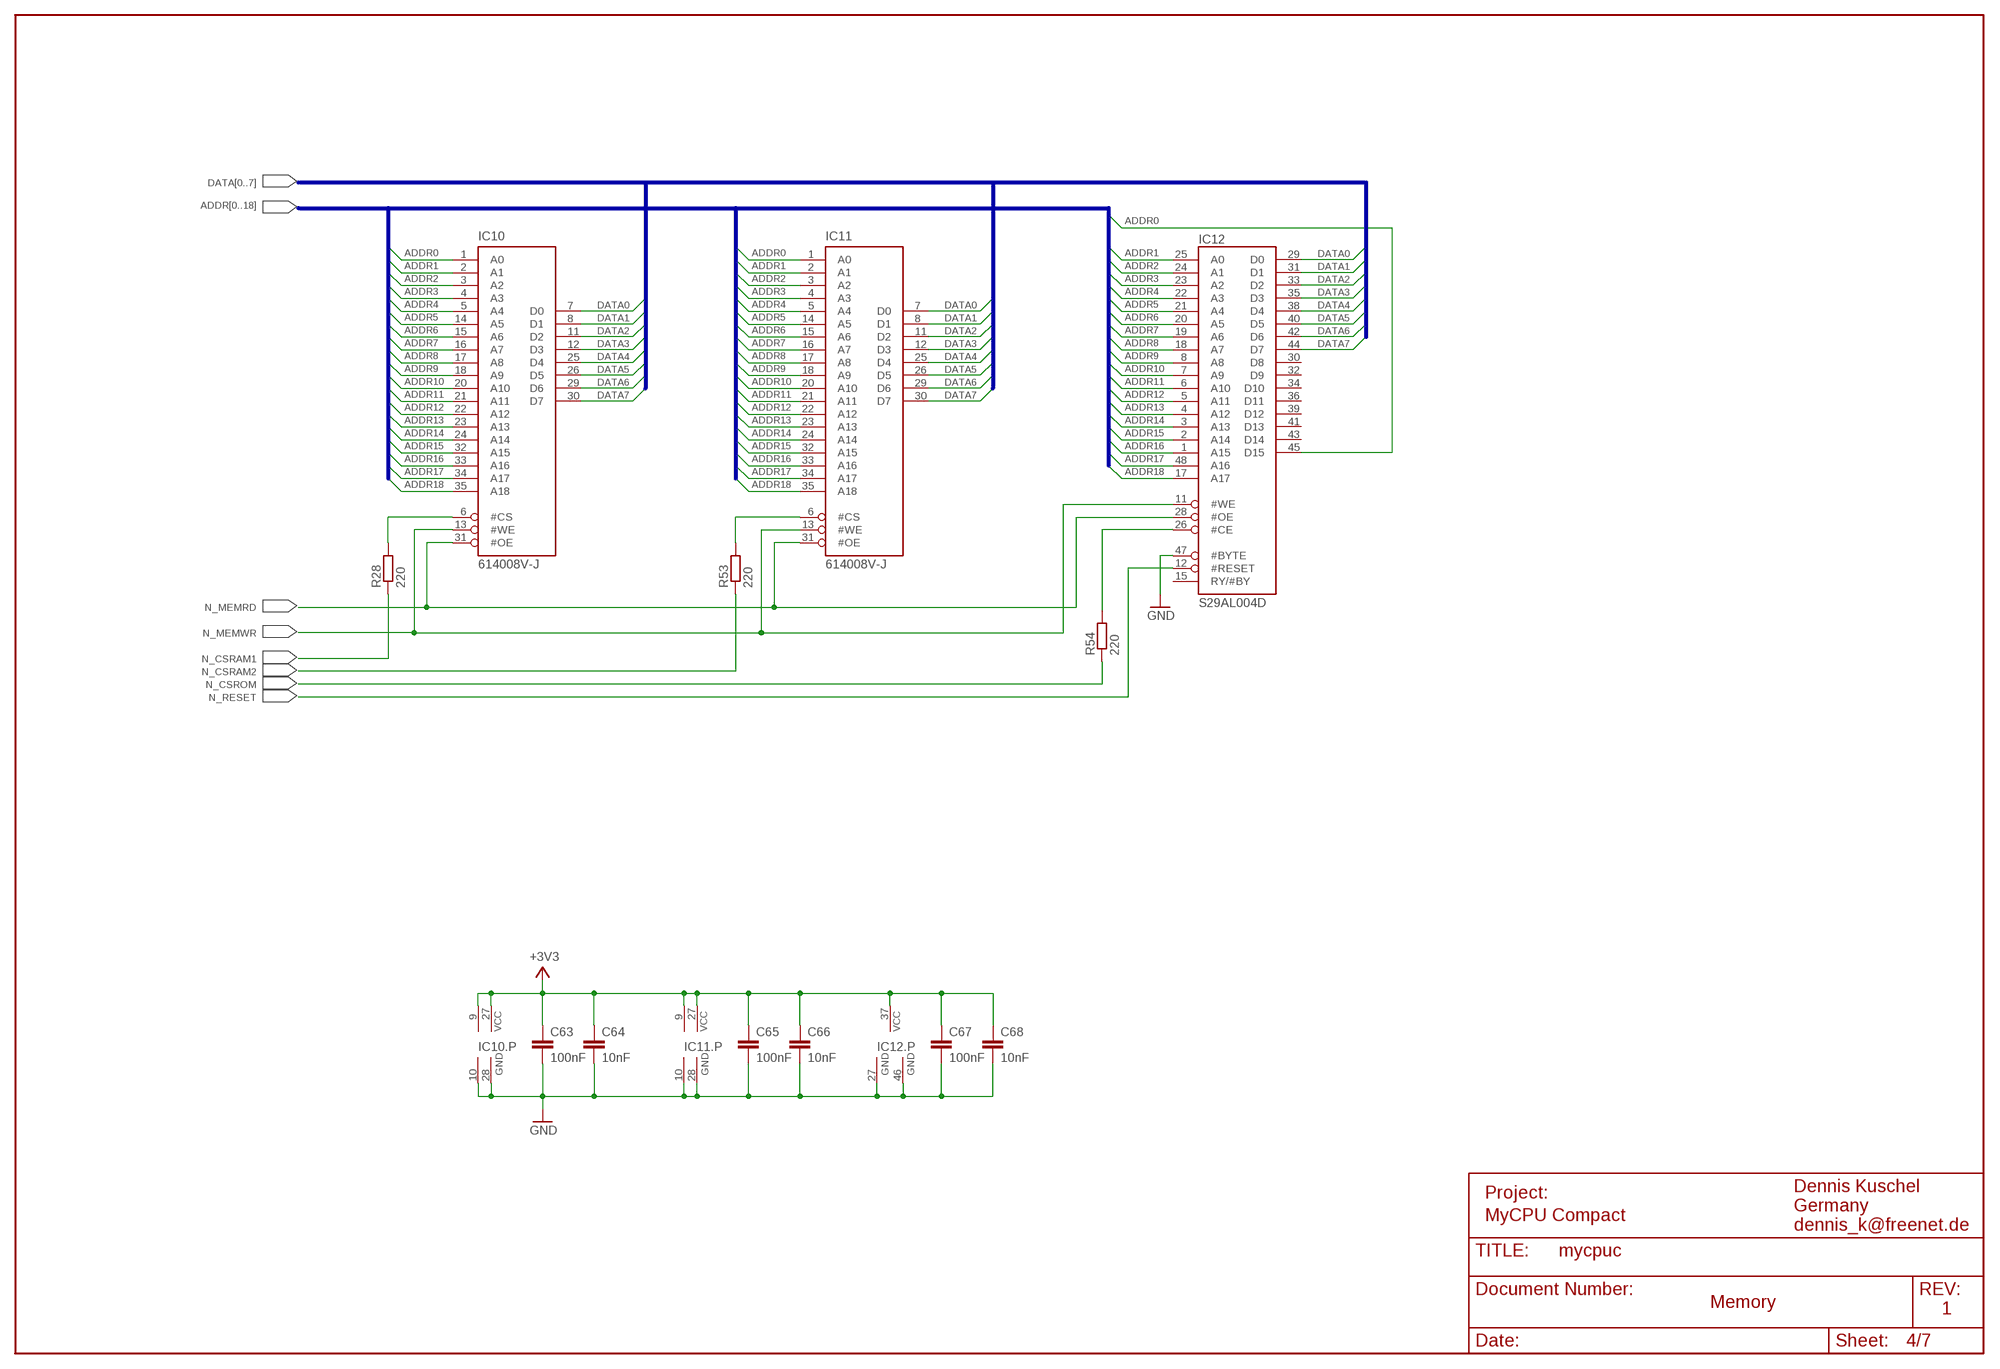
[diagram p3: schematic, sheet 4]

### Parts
C63  100nF  C-EUC0805  [C0805]
C64  10nF  C-EUC0805  [C0805]
C65  100nF  C-EUC0805  [C0805]
C66  10nF  C-EUC0805  [C0805]
C67  100nF  C-EUC0805  [C0805]
C68  10nF  C-EUC0805  [C0805]
IC10  614008V-J  [SOJ36]
IC11  614008V-J  [SOJ36]
IC12  S29AL004D  [TSOP48]
R28  220  R-EU_R0805  [R0805]
R53  220  R-EU_R0805  [R0805]
R54  220  R-EU_R0805  [R0805]

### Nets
+3V3: C63.1 C64.1 C65.1 C66.1 C67.1 C68.1 IC10.9(VCC) IC10.27(VCC) IC11.9(VCC) IC11.27(VCC) IC12.37(VCC) ; also sheet 1,2,3,5
ADDR0: IC10.1(A0) IC11.1(A0) IC12.45(D15) ; also sheet 1,3
ADDR1: IC10.2(A1) IC11.2(A1) IC12.25(A0) ; also sheet 1,3
ADDR2: IC10.3(A2) IC11.3(A2) IC12.24(A1) ; also sheet 1,3
ADDR3: IC10.4(A3) IC11.4(A3) IC12.23(A2) ; also sheet 1,3
ADDR4: IC10.5(A4) IC11.5(A4) IC12.22(A3) ; also sheet 1,3
ADDR5: IC10.14(A5) IC11.14(A5) IC12.21(A4) ; also sheet 1,3
ADDR6: IC10.15(A6) IC11.15(A6) IC12.20(A5) ; also sheet 1,3
ADDR7: IC10.16(A7) IC11.16(A7) IC12.19(A6) ; also sheet 1,3
ADDR8: IC10.17(A8) IC11.17(A8) IC12.18(A7) ; also sheet 1,3
ADDR9: IC10.18(A9) IC11.18(A9) IC12.8(A8) ; also sheet 1,3
ADDR10: IC10.20(A10) IC11.20(A10) IC12.7(A9) ; also sheet 1,3
ADDR11: IC10.21(A11) IC11.21(A11) IC12.6(A10) ; also sheet 1,3
ADDR12: IC10.22(A12) IC11.22(A12) IC12.5(A11) ; also sheet 1,3
ADDR13: IC10.23(A13) IC11.23(A13) IC12.4(A12) ; also sheet 1,3
ADDR14: IC10.24(A14) IC11.24(A14) IC12.3(A13) ; also sheet 1,3
ADDR15: IC10.32(A15) IC11.32(A15) IC12.2(A14) ; also sheet 1,3
ADDR16: IC10.33(A16) IC11.33(A16) IC12.1(A15) ; also sheet 1
ADDR17: IC10.34(A17) IC11.34(A17) IC12.48(A16) ; also sheet 1
ADDR18: IC10.35(A18) IC11.35(A18) IC12.17(A17) ; also sheet 1
DATA0: IC10.7(D0) IC11.7(D0) IC12.29(D0) ; also sheet 1,3
DATA1: IC10.8(D1) IC11.8(D1) IC12.31(D1) ; also sheet 1,3
DATA2: IC10.11(D2) IC11.11(D2) IC12.33(D2) ; also sheet 1,3
DATA3: IC10.12(D3) IC11.12(D3) IC12.35(D3) ; also sheet 1,3
DATA4: IC10.25(D4) IC11.25(D4) IC12.38(D4) ; also sheet 1,3
DATA5: IC10.26(D5) IC11.26(D5) IC12.40(D5) ; also sheet 1,3
DATA6: IC10.29(D6) IC11.29(D6) IC12.42(D6) ; also sheet 1,3
DATA7: IC10.30(D7) IC11.30(D7) IC12.44(D7) ; also sheet 1,3
GND: C63.2 C64.2 C65.2 C66.2 C67.2 C68.2 IC10.10(GND) IC10.28(GND) IC11.10(GND) IC11.28(GND) IC12.27(GND) IC12.46(GND) IC12.47(#BYTE) ; also sheet 1,2,3,5,6,7
N$20: IC11.6(#CS) R53.2
N$21: IC12.26(#CE) R54.2
N$22: IC10.6(#CS) R28.2
N_CSRAM1: R28.1 ; also sheet 1
N_CSRAM2: R53.1 ; also sheet 1
N_CSROM: R54.1 ; also sheet 1
N_MEMRD: IC10.31(#OE) IC11.31(#OE) IC12.28(#OE) ; also sheet 1
N_MEMWR: IC10.13(#WE) IC11.13(#WE) IC12.11(#WE) ; also sheet 1
N_RESET: IC12.12(#RESET) ; also sheet 1
Unconnected: IC10.19(NC) IC10.36(NC1) IC11.19(NC) IC11.36(NC1) IC12.9(NC.1) IC12.10(NC.2) IC12.13(NC.3) IC12.14(NC.4) IC12.15(RY/#BY) IC12.16(NC.5) IC12.30(D8) IC12.32(D9) IC12.34(D10) IC12.36(D11) IC12.39(D12) IC12.41(D13) IC12.43(D14)

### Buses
ADDR[0..18]
DATA[0..7]

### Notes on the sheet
- Dennis Kuschel
- Project:
- Germany
- MyCPU Compact
- dennis_k@freenet.de
- Memory
- 1

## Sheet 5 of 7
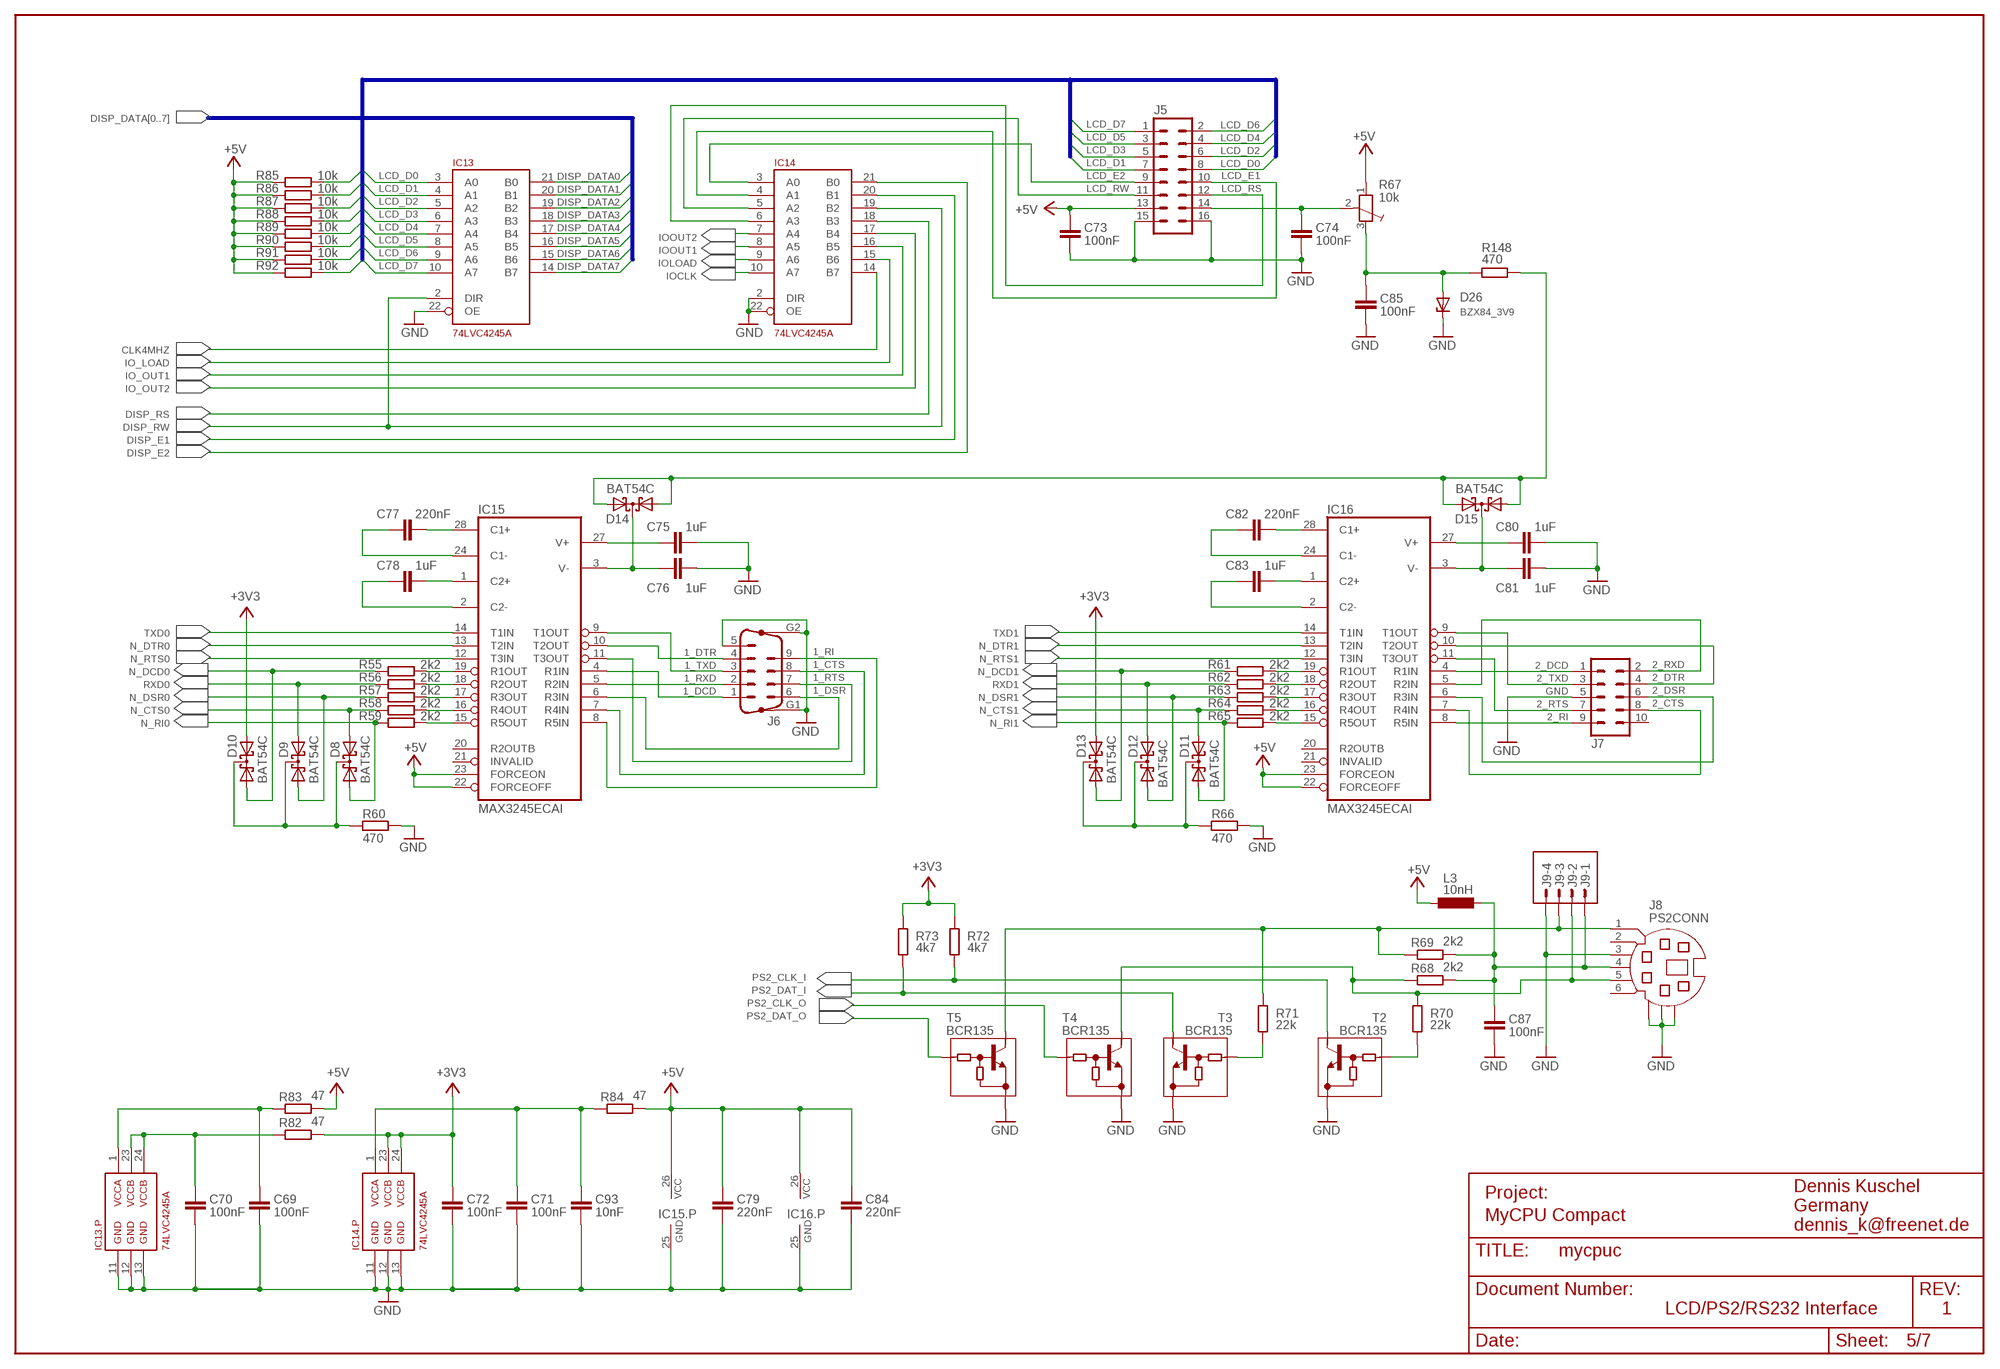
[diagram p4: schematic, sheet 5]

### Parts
C69  100nF  C-EUC0805  [C0805]
C70  100nF  C-EUC0805  [C0805]
C71  100nF  C-EUC0805  [C0805]
C72  100nF  C-EUC0805  [C0805]
C73  100nF  C-EUC0805  [C0805]
C74  100nF  C-EUC0805  [C0805]
C75  1uF  C-EUC0805  [C0805]
C76  1uF  C-EUC0805  [C0805]
C77  220nF  C-EUC0805  [C0805]
C78  1uF  C-EUC0805  [C0805]
C79  220nF  C-EUC0805  [C0805]
C80  1uF  C-EUC0805  [C0805]
C81  1uF  C-EUC0805  [C0805]
C82  220nF  C-EUC0805  [C0805]
C83  1uF  C-EUC0805  [C0805]
C84  220nF  C-EUC0805  [C0805]
C85  100nF  C-EUC0805  [C0805]
C87  100nF  C-EUC0805  [C0805]
C93  10nF  C-EUC0805  [C0805]
D8  BAT54C  BAS40-05  [SOT23]
D9  BAT54C  BAS40-05  [SOT23]
D10  BAT54C  BAS40-05  [SOT23]
D11  BAT54C  BAS40-05  [SOT23]
D12  BAT54C  BAS40-05  [SOT23]
D13  BAT54C  BAS40-05  [SOT23]
D14  BAT54C  BAS40-05  [SOT23]
D15  BAT54C  BAS40-05  [SOT23]
D26  BZX84_3V9  BZX84CSMD  [TO236]
IC13  74LVC4245A  [TSSOP24]
IC14  74LVC4245A  [TSSOP24]
IC15  MAX3245ECAI  [SSOP28]
IC16  MAX3245ECAI  [SSOP28]
J5  ML16L  [ML16L]
J6  M09HP  [M09HP]
J7  ML10  [ML10]
J8  PS2CONN  [MINIDIN-6]
J9  S04P  [S04P]
L3  10nH  L-0805  [0805]
R55  2k2  R-EU_R0805  [R0805]
R56  2k2  R-EU_R0805  [R0805]
R57  2k2  R-EU_R0805  [R0805]
R58  2k2  R-EU_R0805  [R0805]
R59  2k2  R-EU_R0805  [R0805]
R60  470  R-EU_R0805  [R0805]
R61  2k2  R-EU_R0805  [R0805]
R62  2k2  R-EU_R0805  [R0805]
R63  2k2  R-EU_R0805  [R0805]
R64  2k2  R-EU_R0805  [R0805]
R65  2k2  R-EU_R0805  [R0805]
R66  470  R-EU_R0805  [R0805]
R67  10k  PT6-L  [PT-6L]
R68  2k2  R-EU_R0805  [R0805]
R69  2k2  R-EU_R0805  [R0805]
R70  22k  R-EU_R0805  [R0805]
R71  22k  R-EU_R0805  [R0805]
R72  4k7  R-EU_R0805  [R0805]
R73  4k7  R-EU_R0805  [R0805]
R82  47  R-EU_R0805  [R0805]
R83  47  R-EU_R0805  [R0805]
R84  47  R-EU_R0805  [R0805]
R85  10k  R-EU_R0805  [R0805]
R86  10k  R-EU_R0805  [R0805]
R87  10k  R-EU_R0805  [R0805]
R88  10k  R-EU_R0805  [R0805]
R89  10k  R-EU_R0805  [R0805]
R90  10k  R-EU_R0805  [R0805]
R91  10k  R-EU_R0805  [R0805]
R92  10k  R-EU_R0805  [R0805]
R148  470  R-EU_R0805  [R0805]
T2  BCR135  [SOT23]
T3  BCR135  [SOT23]
T4  BCR135  [SOT23]
T5  BCR135  [SOT23]

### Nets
1_CTS: IC15.7(R4IN) J6.8
1_DCD: IC15.4(R1IN) J6.1
1_DSR: IC15.6(R3IN) J6.6
1_DTR: IC15.10(T2OUT) J6.4
1_RI: IC15.8(R5IN) J6.9
1_RTS: IC15.11(T3OUT) J6.7
1_RXD: IC15.5(R2IN) J6.2
1_TXD: IC15.9(T1OUT) J6.3
2_CTS: IC16.7(R4IN) J7.8
2_DCD: IC16.4(R1IN) J7.1
2_DSR: IC16.6(R3IN) J7.6
2_DTR: IC16.10(T2OUT) J7.4
2_RI: IC16.8(R5IN) J7.9
2_RTS: IC16.11(T3OUT) J7.7
2_RXD: IC16.5(R2IN) J7.2
2_TXD: IC16.9(T1OUT) J7.3
5VKBD: C87.1 J8.4 J9.1 L3.1 R68.2 R69.2
+3V3: C72.1 D10.2(A2) D13.2(A2) IC14.23(VCCB.1) IC14.24(VCCB.2) R72.2 R73.2 R82.2 ; also sheet 1,2,3,4
+5V: C73.1 C79.1 C84.1 IC15.22(FORCEOFF) IC15.23(FORCEON) IC15.26(VCC) IC16.22(FORCEOFF) IC16.23(FORCEON) IC16.26(VCC) J5.13 L3.2 R67.1 R83.2 R84.2 R85.1 R86.1 R87.1 R88.1 R89.1 R90.1 R91.1 R92.1 ; also sheet 1,2,3,6,7
-5V: C85.1 D26.A R67.3 R148.1
-10V: D14.1(A1) D14.2(A2) D15.1(A1) D15.2(A2) R148.2
CLK4MHZ: IC14.14(B7) ; also sheet 1,3
DISP_DATA0: IC13.21(B0) ; also sheet 1
DISP_DATA1: IC13.20(B1) ; also sheet 1
DISP_DATA2: IC13.19(B2) ; also sheet 1
DISP_DATA3: IC13.18(B3) ; also sheet 1
DISP_DATA4: IC13.17(B4) ; also sheet 1
DISP_DATA5: IC13.16(B5) ; also sheet 1
DISP_DATA6: IC13.15(B6) ; also sheet 1
DISP_DATA7: IC13.14(B7) ; also sheet 1
DISP_E1: IC14.20(B1) ; also sheet 1
DISP_E2: IC14.21(B0) ; also sheet 1
DISP_RS: IC14.18(B3) ; also sheet 1
DISP_RW: IC13.2(DIR) IC14.19(B2) ; also sheet 1
GND: C69.2 C70.2 C71.2 C72.2 C73.2 C74.2 C75.2 C76.2 C79.2 C80.2 C81.2 C84.2 C85.2 C87.2 C93.2 D26.C IC13.11(GND.1) IC13.12(GND.2) IC13.13(GND.3) IC13.22(OE) IC14.2(DIR) IC14.11(GND.1) IC14.12(GND.2) IC14.13(GND.3) IC14.22(OE) IC15.25(GND) IC16.25(GND) J5.15 J5.16 J6.5 J6.G1 J6.G2 J7.5 J8.3 J8.SHIELD.1 J8.SHIELD.2 J8.SHIELD.3 J9.4 R60.2 R66.2 T2.2(E) T3.2(E) T4.2(E) T5.2(E) ; also sheet 1,2,3,4,6,7
IO_LOAD: IC14.15(B6) ; also sheet 1
IO_OUT1: IC14.16(B5) ; also sheet 1
IO_OUT2: IC14.17(B4) ; also sheet 1
IOCLK: IC14.10(A7) ; also sheet 6
IOLOAD: IC14.9(A6) ; also sheet 6
IOOUT1: IC14.8(A5) ; also sheet 6
IOOUT2: IC14.7(A4) ; also sheet 6
LCD_D0: IC13.3(A0) J5.8 R85.2
LCD_D1: IC13.4(A1) J5.7 R86.2
LCD_D2: IC13.5(A2) J5.6 R87.2
LCD_D3: IC13.6(A3) J5.5 R88.2
LCD_D4: IC13.7(A4) J5.4 R89.2
LCD_D5: IC13.8(A5) J5.3 R90.2
LCD_D6: IC13.9(A6) J5.2 R91.2
LCD_D7: IC13.10(A7) J5.1 R92.2
LCD_E1: IC14.4(A1) J5.10
LCD_E2: IC14.3(A0) J5.9
LCD_RS: IC14.6(A3) J5.12
LCD_RW: IC14.5(A2) J5.11
N$23: C74.1 J5.14 R67.2
N$24: IC15.19(R1OUT) R55.2
N$25: C75.1 IC15.27(V+)
N$26: C76.1 D14.3(C) IC15.3(V-)
N$27: IC15.18(R2OUT) R56.2
N$28: C77.2 IC15.28(C1+)
N$29: C77.1 IC15.24(C1-)
N$30: C78.2 IC15.1(C2+)
N$31: C78.1 IC15.2(C2-)
N$32: IC15.17(R3OUT) R57.2
N$33: IC15.16(R4OUT) R58.2
N$34: IC15.15(R5OUT) R59.2
N$36: D8.3(C) D9.3(C) D10.3(C) R60.1
N$37: R70.1 T2.1(B)
N$38: C80.1 IC16.27(V+)
N$39: C81.1 D15.3(C) IC16.3(V-)
N$40: C82.2 IC16.28(C1+)
N$41: C82.1 IC16.24(C1-)
N$42: C83.2 IC16.1(C2+)
N$43: C83.1 IC16.2(C2-)
N$44: IC16.19(R1OUT) R61.2
N$45: IC16.18(R2OUT) R62.2
N$46: IC16.17(R3OUT) R63.2
N$47: IC16.16(R4OUT) R64.2
N$48: IC16.15(R5OUT) R65.2
N$49: D11.3(C) D12.3(C) D13.3(C) R66.1
N$50: R71.1 T3.1(B)
N$61: C70.1 IC13.23(VCCB.1) IC13.24(VCCB.2) R82.1
N$62: C69.1 IC13.1(VCCA) R83.1
N$64: C71.1 C93.1 IC14.1(VCCA) R84.1
N_CTS0: D8.2(A2) R58.1 ; also sheet 1
N_CTS1: D11.1(A1) R64.1 ; also sheet 1
N_DCD0: D10.1(A1) R55.1 ; also sheet 1
N_DCD1: D13.1(A1) R61.1 ; also sheet 1
N_DSR0: D9.1(A1) R57.1 ; also sheet 1
N_DSR1: D12.2(A2) R63.1 ; also sheet 1
N_DTR0: IC15.13(T2IN) ; also sheet 1
N_DTR1: IC16.13(T2IN) ; also sheet 1
N_RI0: D8.1(A1) R59.1 ; also sheet 1
N_RI1: D11.2(A2) R65.1 ; also sheet 1
N_RTS0: IC15.12(T3IN) ; also sheet 1
N_RTS1: IC16.12(T3IN) ; also sheet 1
PS2_CLK: J8.5 J9.2 R68.1 R70.2 T4.3(C)
PS2_CLK_I: R72.1 T2.3(C) ; also sheet 1
PS2_CLK_O: T4.1(B) ; also sheet 1
PS2_DAT_I: R73.1 T3.3(C) ; also sheet 1
PS2_DAT_O: T5.1(B) ; also sheet 1
PS2_DATA: J8.1 J9.3 R69.1 R71.2 T5.3(C)
RXD0: D9.2(A2) R56.1 ; also sheet 1
RXD1: D12.1(A1) R62.1 ; also sheet 1
TXD0: IC15.14(T1IN) ; also sheet 1
TXD1: IC16.14(T1IN) ; also sheet 1
Unconnected: IC15.20(R2OUTB) IC15.21(INVALID) IC16.20(R2OUTB) IC16.21(INVALID) J7.10 J8.2 J8.6

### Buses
DISP_DATA[0..7]
LCD_D[0..7]

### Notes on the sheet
- Dennis Kuschel
- Project:
- Germany
- MyCPU Compact
- dennis_k@freenet.de
- LCD/PS2/RS232 Interface | 1

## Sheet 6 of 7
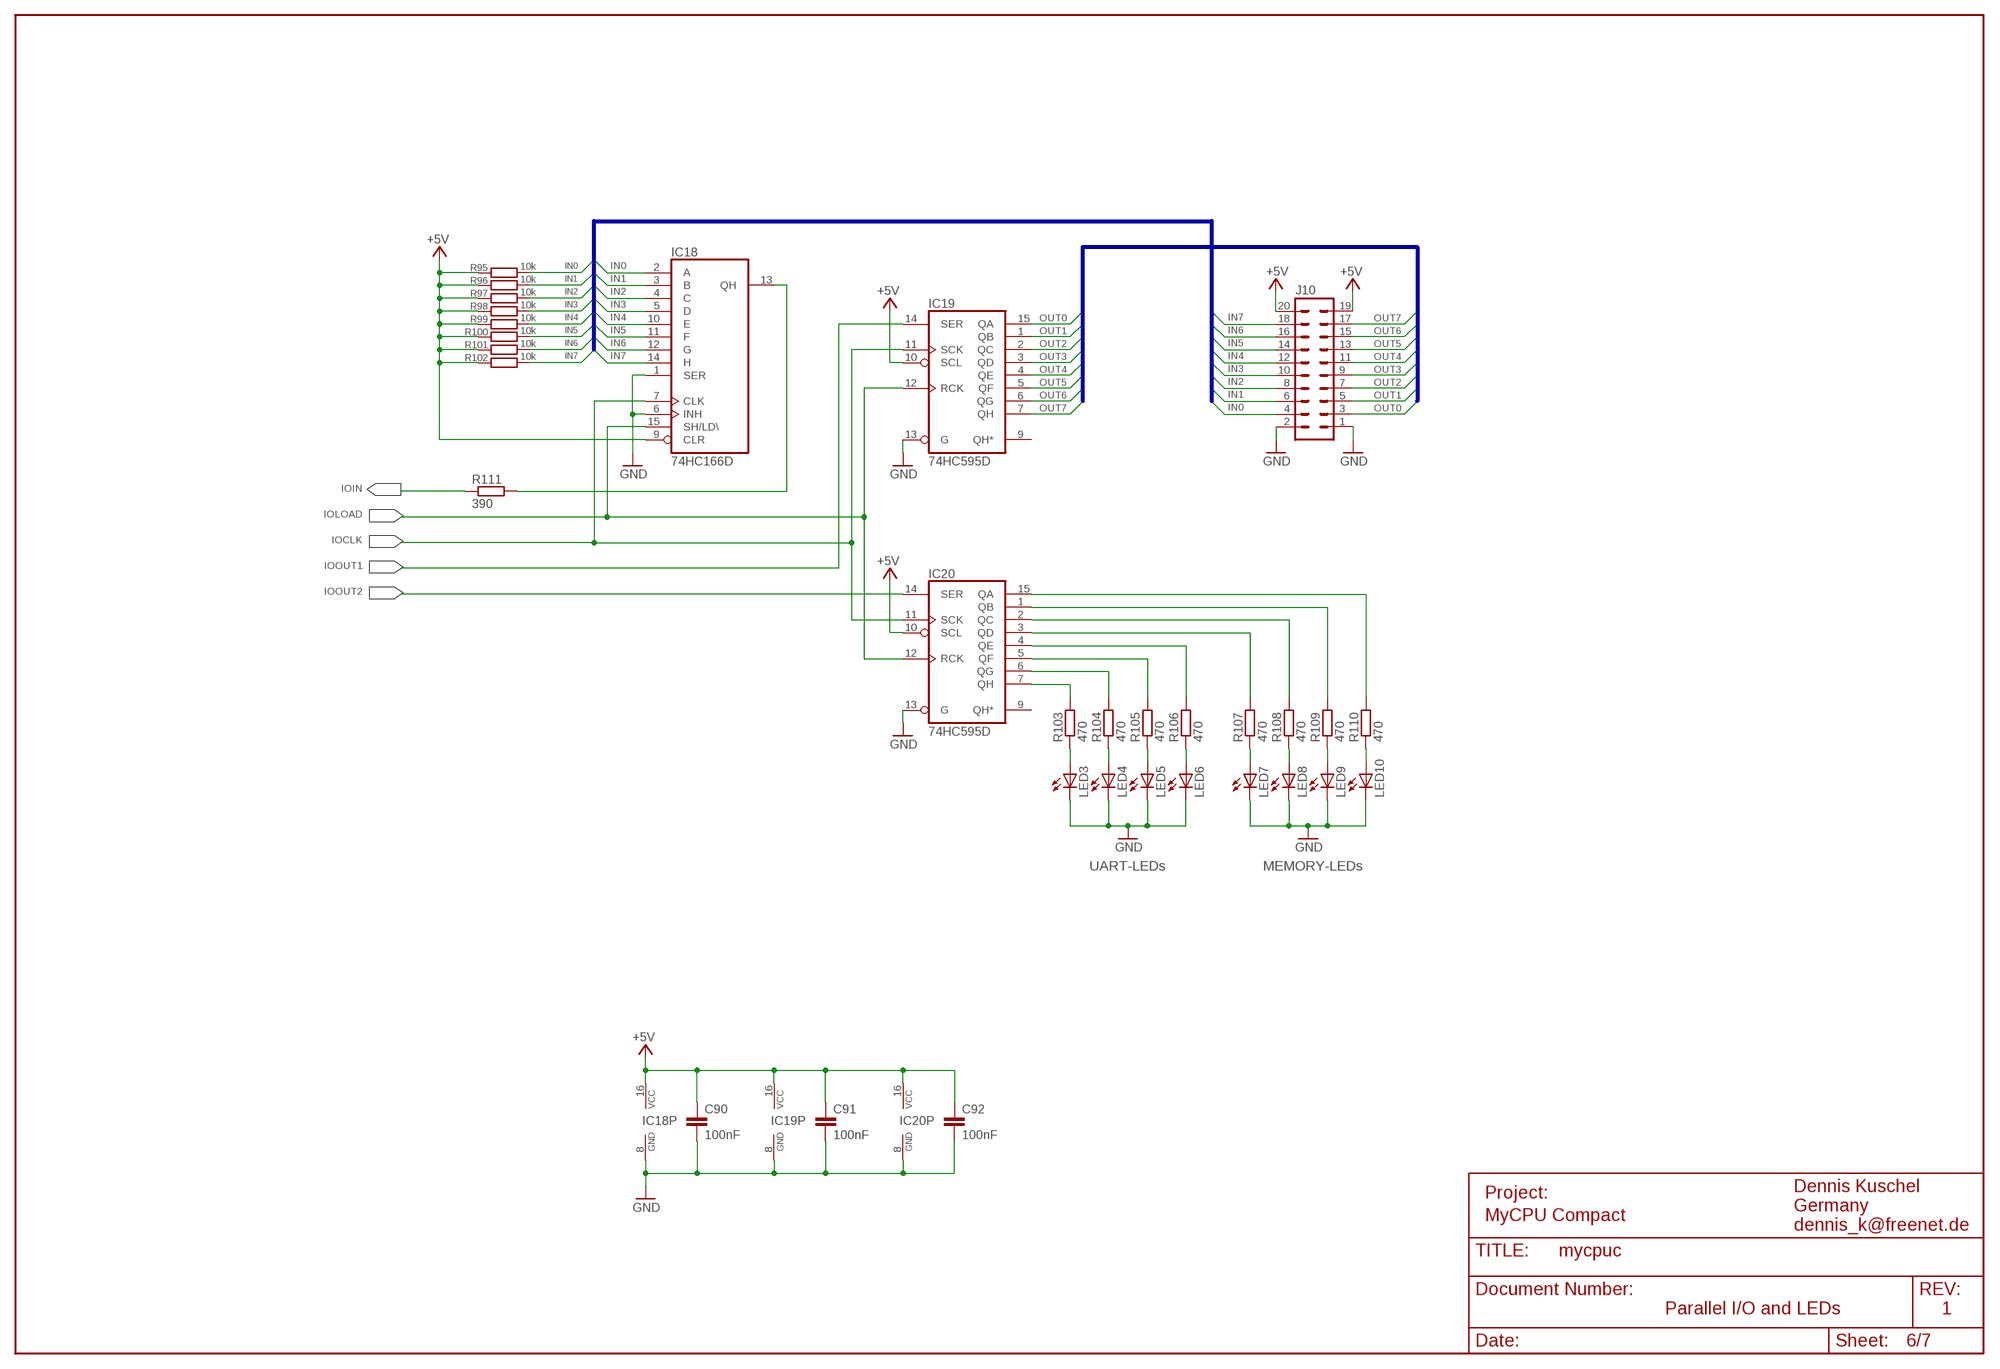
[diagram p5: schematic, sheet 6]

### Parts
C90  100nF  C-EUC0805  [C0805]
C91  100nF  C-EUC0805  [C0805]
C92  100nF  C-EUC0805  [C0805]
IC18  74HC166D  [SO16]
IC19  74HC595D  [SO16]
IC20  74HC595D  [SO16]
J10  ML20  [ML20]
LED3  LEDCHIP-LED0805  [CHIP-LED0805]
LED4  LEDCHIP-LED0805  [CHIP-LED0805]
LED5  LEDCHIP-LED0805  [CHIP-LED0805]
LED6  LEDCHIP-LED0805  [CHIP-LED0805]
LED7  LEDCHIP-LED0805  [CHIP-LED0805]
LED8  LEDCHIP-LED0805  [CHIP-LED0805]
LED9  LEDCHIP-LED0805  [CHIP-LED0805]
LED10  LEDCHIP-LED0805  [CHIP-LED0805]
R95  10k  R-EU_R0805  [R0805]
R96  10k  R-EU_R0805  [R0805]
R97  10k  R-EU_R0805  [R0805]
R98  10k  R-EU_R0805  [R0805]
R99  10k  R-EU_R0805  [R0805]
R100  10k  R-EU_R0805  [R0805]
R101  10k  R-EU_R0805  [R0805]
R102  10k  R-EU_R0805  [R0805]
R103  470  R-EU_R0805  [R0805]
R104  470  R-EU_R0805  [R0805]
R105  470  R-EU_R0805  [R0805]
R106  470  R-EU_R0805  [R0805]
R107  470  R-EU_R0805  [R0805]
R108  470  R-EU_R0805  [R0805]
R109  470  R-EU_R0805  [R0805]
R110  470  R-EU_R0805  [R0805]
R111  390  R-EU_R0805  [R0805]

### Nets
+5V: C90.1 C91.1 C92.1 IC18.9(CLR) IC18.16(VCC) IC19.10(SCL) IC19.16(VCC) IC20.10(SCL) IC20.16(VCC) J10.19 J10.20 R95.1 R96.1 R97.1 R98.1 R99.1 R100.1 R101.1 R102.1 ; also sheet 1,2,3,5,7
GND: C90.2 C91.2 C92.2 IC18.1(SER) IC18.6(INH) IC18.8(GND) IC19.8(GND) IC19.13(G) IC20.8(GND) IC20.13(G) J10.1 J10.2 LED3.C LED4.C LED5.C LED6.C LED7.C LED8.C LED9.C LED10.C ; also sheet 1,2,3,4,5,7
IN0: IC18.2(A) J10.4 R95.2
IN1: IC18.3(B) J10.6 R96.2
IN2: IC18.4(C) J10.8 R97.2
IN3: IC18.5(D) J10.10 R98.2
IN4: IC18.10(E) J10.12 R99.2
IN5: IC18.11(F) J10.14 R100.2
IN6: IC18.12(G) J10.16 R101.2
IN7: IC18.14(H) J10.18 R102.2
IOCLK: IC18.7(CLK) IC19.11(SCK) IC20.11(SCK) ; also sheet 5
IOIN: R111.1 ; also sheet 1,3
IOLOAD: IC18.15(SH/LD\) IC19.12(RCK) IC20.12(RCK) ; also sheet 5
IOOUT1: IC19.14(SER) ; also sheet 5
IOOUT2: IC20.14(SER) ; also sheet 5
N$67: IC18.13(QH) R111.2
N$70: LED3.A R103.1
N$71: LED4.A R104.1
N$72: LED5.A R105.1
N$73: LED6.A R106.1
N$74: LED7.A R107.1
N$75: LED8.A R108.1
N$76: LED9.A R109.1
N$77: LED10.A R110.1
N$78: IC20.7(QH) R103.2
N$79: IC20.6(QG) R104.2
N$80: IC20.5(QF) R105.2
N$81: IC20.4(QE) R106.2
N$82: IC20.3(QD) R107.2
N$83: IC20.2(QC) R108.2
N$84: IC20.1(QB) R109.2
N$85: IC20.15(QA) R110.2
OUT0: IC19.15(QA) J10.3
OUT1: IC19.1(QB) J10.5
OUT2: IC19.2(QC) J10.7
OUT3: IC19.3(QD) J10.9
OUT4: IC19.4(QE) J10.11
OUT5: IC19.5(QF) J10.13
OUT6: IC19.6(QG) J10.15
OUT7: IC19.7(QH) J10.17
Unconnected: IC19.9(QH*) IC20.9(QH*)

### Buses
IN[0..7]
OUT[0..7]

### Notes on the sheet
- UART-LEDs | MEMORY-LEDs
- Dennis Kuschel
- Project:
- Germany
- MyCPU Compact
- dennis_k@freenet.de
- Parallel I/O and LEDs | 1

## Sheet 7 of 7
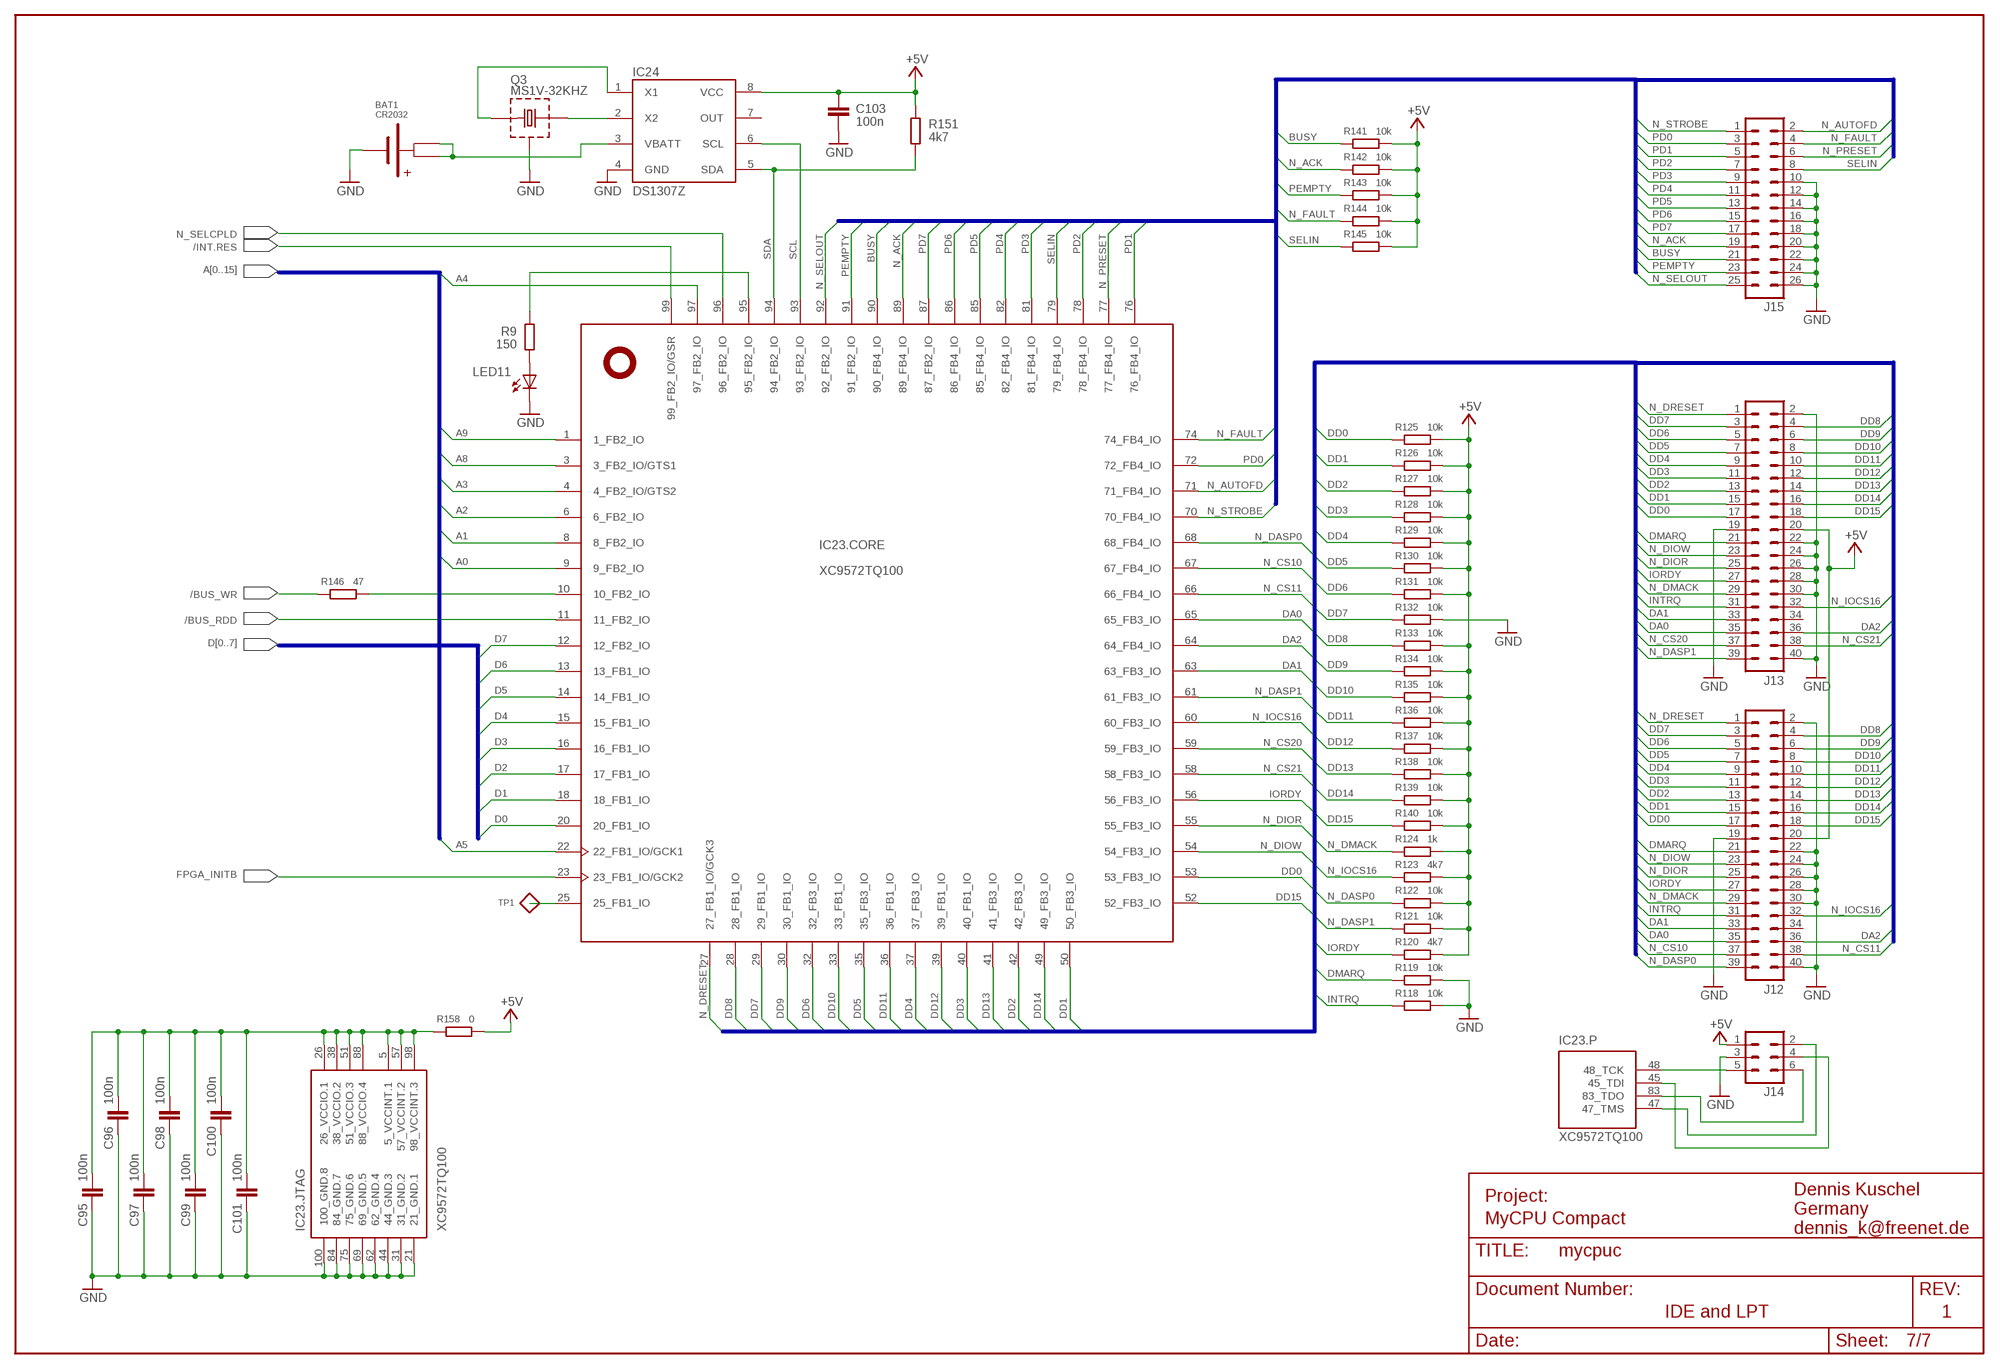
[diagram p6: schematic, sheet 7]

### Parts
BAT1  CR2032  BAT3VH  [BATH]
C95  100n  C-EUC0805  [C0805]
C96  100n  C-EUC0805  [C0805]
C97  100n  C-EUC0805  [C0805]
C98  100n  C-EUC0805  [C0805]
C99  100n  C-EUC0805  [C0805]
C100  100n  C-EUC0805  [C0805]
C101  100n  C-EUC0805  [C0805]
C103  100n  C-EUC0805  [C0805]
IC23  XC9572TQ100  [TQFP100]
IC24  DS1307Z  [SO8]
J12  ML40L  [ML40L]
J13  ML40  [ML40]
J14  ML6  [ML6]
J15  ML26  [ML26]
LED11  LEDCHIP-LED0805  [CHIP-LED0805]
Q3  MS1V-32KHZ  [MS1V]
R9  150  R-EU_M0805  [M0805]
R118  10k  R-EU_M0805  [M0805]
R119  10k  R-EU_M0805  [M0805]
R120  4k7  R-EU_M0805  [M0805]
R121  10k  R-EU_M0805  [M0805]
R122  10k  R-EU_M0805  [M0805]
R123  4k7  R-EU_M0805  [M0805]
R124  1k  R-EU_M0805  [M0805]
R125  10k  R-EU_M0805  [M0805]
R126  10k  R-EU_M0805  [M0805]
R127  10k  R-EU_M0805  [M0805]
R128  10k  R-EU_M0805  [M0805]
R129  10k  R-EU_M0805  [M0805]
R130  10k  R-EU_M0805  [M0805]
R131  10k  R-EU_M0805  [M0805]
R132  10k  R-EU_M0805  [M0805]
R133  10k  R-EU_M0805  [M0805]
R134  10k  R-EU_M0805  [M0805]
R135  10k  R-EU_M0805  [M0805]
R136  10k  R-EU_M0805  [M0805]
R137  10k  R-EU_M0805  [M0805]
R138  10k  R-EU_M0805  [M0805]
R139  10k  R-EU_M0805  [M0805]
R140  10k  R-EU_M0805  [M0805]
R141  10k  R-EU_M0805  [M0805]
R142  10k  R-EU_M0805  [M0805]
R143  10k  R-EU_M0805  [M0805]
R144  10k  R-EU_M0805  [M0805]
R145  10k  R-EU_M0805  [M0805]
R146  47  R-EU_M0805  [M0805]
R151  4k7  R-EU_M0805  [M0805]
R158  0  R-EU_M0805  [M0805]
TP1  TESTPAD1  [TEST-PAD]

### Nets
5V_CPLD: C95.2 C96.2 C97.2 C98.2 C99.2 C100.2 C101.2 IC23.5(.JTAG:5_VCCINT.1) IC23.26(.JTAG:26_VCCIO.1) IC23.38(.JTAG:38_VCCIO.2) IC23.51(.JTAG:51_VCCIO.3) IC23.57(.JTAG:57_VCCINT.2) IC23.88(.JTAG:88_VCCIO.4) IC23.98(.JTAG:98_VCCINT.3) R158.1
+5V: C103.2 IC24.8(VCC) J12.20 J13.20 J14.1 R120.2 R121.2 R122.2 R123.2 R124.2 R125.2 R126.2 R127.2 R128.2 R129.2 R130.2 R131.2 R133.2 R134.2 R135.2 R136.2 R137.2 R138.2 R139.2 R140.2 R141.2 R142.2 R143.2 R144.2 R145.2 R151.2 R158.2 ; also sheet 1,2,3,5,6
/BUS_RDD: IC23.11(.CORE:11_FB2_IO) ; also sheet 3
/BUS_WR: R146.1 ; also sheet 3
/INT.RES: IC23.99(.CORE:99_FB2_IO/GSR) ; also sheet 3
A0: IC23.9(.CORE:9_FB2_IO) ; also sheet 3
A1: IC23.8(.CORE:8_FB2_IO) ; also sheet 3
A2: IC23.6(.CORE:6_FB2_IO) ; also sheet 3
A3: IC23.4(.CORE:4_FB2_IO/GTS2) ; also sheet 3
A4: IC23.97(.CORE:97_FB2_IO) ; also sheet 3
A5: IC23.22(.CORE:22_FB1_IO/GCK1) ; also sheet 3
A8: IC23.3(.CORE:3_FB2_IO/GTS1) ; also sheet 3
A9: IC23.1(.CORE:1_FB2_IO) ; also sheet 3
BUSY: IC23.90(.CORE:90_FB4_IO) J15.21 R141.1
C_TCK: IC23.48(.P:48_TCK) J14.5
C_TDI: IC23.45(.P:45_TDI) J14.4
C_TDO: IC23.83(.P:83_TDO) J14.6
C_TMS: IC23.47(.P:47_TMS) J14.2
D0: IC23.20(.CORE:20_FB1_IO) ; also sheet 3
D1: IC23.18(.CORE:18_FB1_IO) ; also sheet 3
D2: IC23.17(.CORE:17_FB1_IO) ; also sheet 3
D3: IC23.16(.CORE:16_FB1_IO) ; also sheet 3
D4: IC23.15(.CORE:15_FB1_IO) ; also sheet 3
D5: IC23.14(.CORE:14_FB1_IO) ; also sheet 3
D6: IC23.13(.CORE:13_FB1_IO) ; also sheet 3
D7: IC23.12(.CORE:12_FB2_IO) ; also sheet 3
DA0: IC23.65(.CORE:65_FB3_IO) J12.35 J13.35
DA1: IC23.63(.CORE:63_FB3_IO) J12.33 J13.33
DA2: IC23.64(.CORE:64_FB4_IO) J12.36 J13.36
DD0: IC23.53(.CORE:53_FB3_IO) J12.17 J13.17 R125.1
DD1: IC23.50(.CORE:50_FB3_IO) J12.15 J13.15 R126.1
DD2: IC23.42(.CORE:42_FB3_IO) J12.13 J13.13 R127.1
DD3: IC23.40(.CORE:40_FB1_IO) J12.11 J13.11 R128.1
DD4: IC23.37(.CORE:37_FB3_IO) J12.9 J13.9 R129.1
DD5: IC23.35(.CORE:35_FB3_IO) J12.7 J13.7 R130.1
DD6: IC23.32(.CORE:32_FB3_IO) J12.5 J13.5 R131.1
DD7: IC23.29(.CORE:29_FB1_IO) J12.3 J13.3 R132.1
DD8: IC23.28(.CORE:28_FB1_IO) J12.4 J13.4 R133.1
DD9: IC23.30(.CORE:30_FB1_IO) J12.6 J13.6 R134.1
DD10: IC23.33(.CORE:33_FB1_IO) J12.8 J13.8 R135.1
DD11: IC23.36(.CORE:36_FB1_IO) J12.10 J13.10 R136.1
DD12: IC23.39(.CORE:39_FB1_IO) J12.12 J13.12 R137.1
DD13: IC23.41(.CORE:41_FB3_IO) J12.14 J13.14 R138.1
DD14: IC23.49(.CORE:49_FB3_IO) J12.16 J13.16 R139.1
DD15: IC23.52(.CORE:52_FB3_IO) J12.18 J13.18 R140.1
DMARQ: J12.21 J13.21 R119.1
FPGA_INITB: IC23.23(.CORE:23_FB1_IO/GCK2) ; also sheet 1
GND: BAT1.NEG C95.1 C96.1 C97.1 C98.1 C99.1 C100.1 C101.1 C103.1 IC23.21(.JTAG:21_GND.1) IC23.31(.JTAG:31_GND.2) IC23.44(.JTAG:44_GND.3) IC23.62(.JTAG:62_GND.4) IC23.69(.JTAG:69_GND.5) IC23.75(.JTAG:75_GND.6) IC23.84(.JTAG:84_GND.7) IC23.100(.JTAG:100_GND.8) IC24.4(GND) J12.2 J12.19 J12.22 J12.24 J12.26 J12.28 J12.30 J12.40 J13.2 J13.19 J13.22 J13.24 J13.26 J13.28 J13.30 J13.40 J14.3 J15.10 J15.12 J15.14 J15.16 J15.18 J15.20 J15.22 J15.24 J15.26 LED11.C Q3.GND(SHIELD) R118.2 R119.2 R132.2 ; also sheet 1,2,3,4,5,6
INTRQ: J12.31 J13.31 R118.1
IORDY: IC23.56(.CORE:56_FB3_IO) J12.27 J13.27 R120.1
N$12: IC23.95(.CORE:95_FB2_IO) R9.2
N$68: LED11.A R9.1
N$91: IC23.10(.CORE:10_FB2_IO) R146.2
N$101: IC24.2(X2) Q3.1
N$102: IC24.1(X1) Q3.2
N_ACK: IC23.89(.CORE:89_FB4_IO) J15.19 R142.1
N_AUTOFD: IC23.71(.CORE:71_FB4_IO) J15.2
N_CS10: IC23.67(.CORE:67_FB4_IO) J12.37
N_CS11: IC23.66(.CORE:66_FB4_IO) J12.38
N_CS20: IC23.59(.CORE:59_FB3_IO) J13.37
N_CS21: IC23.58(.CORE:58_FB3_IO) J13.38
N_DASP0: IC23.68(.CORE:68_FB4_IO) J12.39 R122.1
N_DASP1: IC23.61(.CORE:61_FB3_IO) J13.39 R121.1
N_DIOR: IC23.55(.CORE:55_FB3_IO) J12.25 J13.25
N_DIOW: IC23.54(.CORE:54_FB3_IO) J12.23 J13.23
N_DMACK: J12.29 J13.29 R124.1
N_DRESET: IC23.27(.CORE:27_FB1_IO/GCK3) J12.1 J13.1
N_FAULT: IC23.74(.CORE:74_FB4_IO) J15.4 R144.1
N_IOCS16: IC23.60(.CORE:60_FB3_IO) J12.32 J13.32 R123.1
N_PRESET: IC23.77(.CORE:77_FB4_IO) J15.6
N_SELCPLD: IC23.96(.CORE:96_FB2_IO) ; also sheet 1
N_SELOUT: IC23.92(.CORE:92_FB2_IO) J15.25
N_STROBE: IC23.70(.CORE:70_FB4_IO) J15.1
PD0: IC23.72(.CORE:72_FB4_IO) J15.3
PD1: IC23.76(.CORE:76_FB4_IO) J15.5
PD2: IC23.78(.CORE:78_FB4_IO) J15.7
PD3: IC23.81(.CORE:81_FB4_IO) J15.9
PD4: IC23.82(.CORE:82_FB4_IO) J15.11
PD5: IC23.85(.CORE:85_FB4_IO) J15.13
PD6: IC23.86(.CORE:86_FB4_IO) J15.15
PD7: IC23.87(.CORE:87_FB2_IO) J15.17
PEMPTY: IC23.91(.CORE:91_FB2_IO) J15.23 R143.1
SCL: IC23.93(.CORE:93_FB2_IO) IC24.6(SCL)
SDA: IC23.94(.CORE:94_FB2_IO) IC24.5(SDA) R151.1
SELIN: IC23.79(.CORE:79_FB4_IO) J15.8 R145.1
VALSN: IC23.25(.CORE:25_FB1_IO) TP1.P$1(TP)
VBAT: BAT1.POS1 BAT1.POS2 IC24.3(VBATT)
Unconnected: IC23.2(.CORE:2_NC.1) IC23.7(.CORE:7_NC.2) IC23.19(.CORE:19_NC.3) IC23.24(.CORE:24_NC.4) IC23.34(.CORE:34_NC.5) IC23.43(.CORE:43_NC.6) IC23.46(.CORE:46_NC.7) IC23.73(.CORE:73_NC.8) IC23.80(.CORE:80_NC.9) IC24.7(OUT) J12.34 J13.34

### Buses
DD[0..15],N_DRESET,N_DIOW,N_DIOR,IORDY,DA2,DA1,DA0,N_CS10,N_CS11,N_CS20,N_CS21,N_DASP0,N_DASP1,N_IOCS16,DMARQ,INTRQ,N_DMACK
PD[0..7],N_SELOUT,SELIN,PEMPTY,BUSY,N_ACK,N_STROBE,N_PRESET,N_FAULT,N_AUTOFD
D[0..7]
A[0..15]

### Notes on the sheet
- Dennis Kuschel
- Project:
- Germany
- MyCPU Compact
- dennis_k@freenet.de
- IDE and LPT | 1

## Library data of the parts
BAT1 = dk-special:BAT3VH
C1 C3-C5 C7 C8 C11 C12 C19-C85 C87-C93 C95-C101 C103 C104 = rcl:C-EU: CAPACITOR, European symbol
C2 C6 C9 C10 C13-C18 = rcl:CPOL-EU: POLARIZED CAPACITOR, European symbol
D1-D19 D22-D25 = diode:BAS40-05: Silicon Schottky Diodes General-purpose diode for high-speed switching
D20 = dk-special:MBRS340
D21 = dk-special:P6SMB68CA
D26 = diode:BZX84CSMD: Z DIODE
F1 = dk-special:FUSE-HASF
H1-H4 = holes:MOUNT-HOLE: MOUNTING HOLE with drill center marker
IC1 = smd-special:XCF02S
IC2 = smd-special:MAX809
IC3 IC4 = smd-special:LT1117-ADJ
IC5 = smd-special:LM2853
IC6-IC9 IC13 IC14 = smd-special:74LVC4245A
IC10 IC11 = smd-special:614008V-J
IC12 = dk-special:S29AL004D
IC15 IC16 = smd-special:MAX3245ECAI
IC18 = 74xx-eu:74*166: 8-bit parallel load SHIFT REGISTER
IC19 IC20 = 74xx-eu:74*595: 8-bit SHIFT REGISTER, output latch
IC21 = xilinx_devices:XC3S400TQ144: Xilinx FPGA: XC3S400tq144
IC23 = dk-special:XC9572TQ100
IC24 = dk-special:DS1307Z
J1 = con-vg:MAC64L: CONNECTOR male, 64 pins, block, type C, rows AC, grid 5.08 mm
J2 J14 = con-harting-ml:ML6: HARTING
J3 = con-amp-mt:S02P: AMP MT CONNECTOR
J4 = con-rib:BU60
J5 = con-harting-ml:ML16: HARTING
J6 = con-subd:M09HP: SUB-D
J7 = con-harting-ml:ML10: HARTING
J8 = dk-special:PS2CONN
J9 = con-amp-mt:S04P: AMP MT CONNECTOR
J10 = con-harting-ml:ML20: HARTING
J11 = con-ptr500:AK500/2: CONNECTOR
J12 J13 = con-harting-ml:ML40: HARTING
J15 = con-harting-ml:ML26: HARTING
JP1 = jump-0r-smd:0R-JUMP: SMD 0R 0805 Jumper
L1 = inductor-coilcraft:DO3316P: COILCRAFT
L2 L6 = smd-special:L-0805
L3-L5 = dk-special:L-0805
LED1-LED11 = led:LED: LED
Q1 Q2 = dk-special:XO91
Q3 = dk-special:MS1V-32KHZ
R1-R66 R68-R148 R151 R154 R155 R158 R159 = rcl:R-EU_: RESISTOR, European symbol
R67 = discrete-my:PT6-L
SW1 = dk-special:DIPSW08-SMD
SW2 = dk-special:KEY-SMS-G
T1 = smd-special:BCR135
T2-T5 = dk-special:BCR135
TP1 = dk-special:TESTPAD1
